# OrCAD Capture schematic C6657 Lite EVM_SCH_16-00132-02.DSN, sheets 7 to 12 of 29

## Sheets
7 PAGE25 : DSP_POWER 2: size C; title: DSP POWER 2
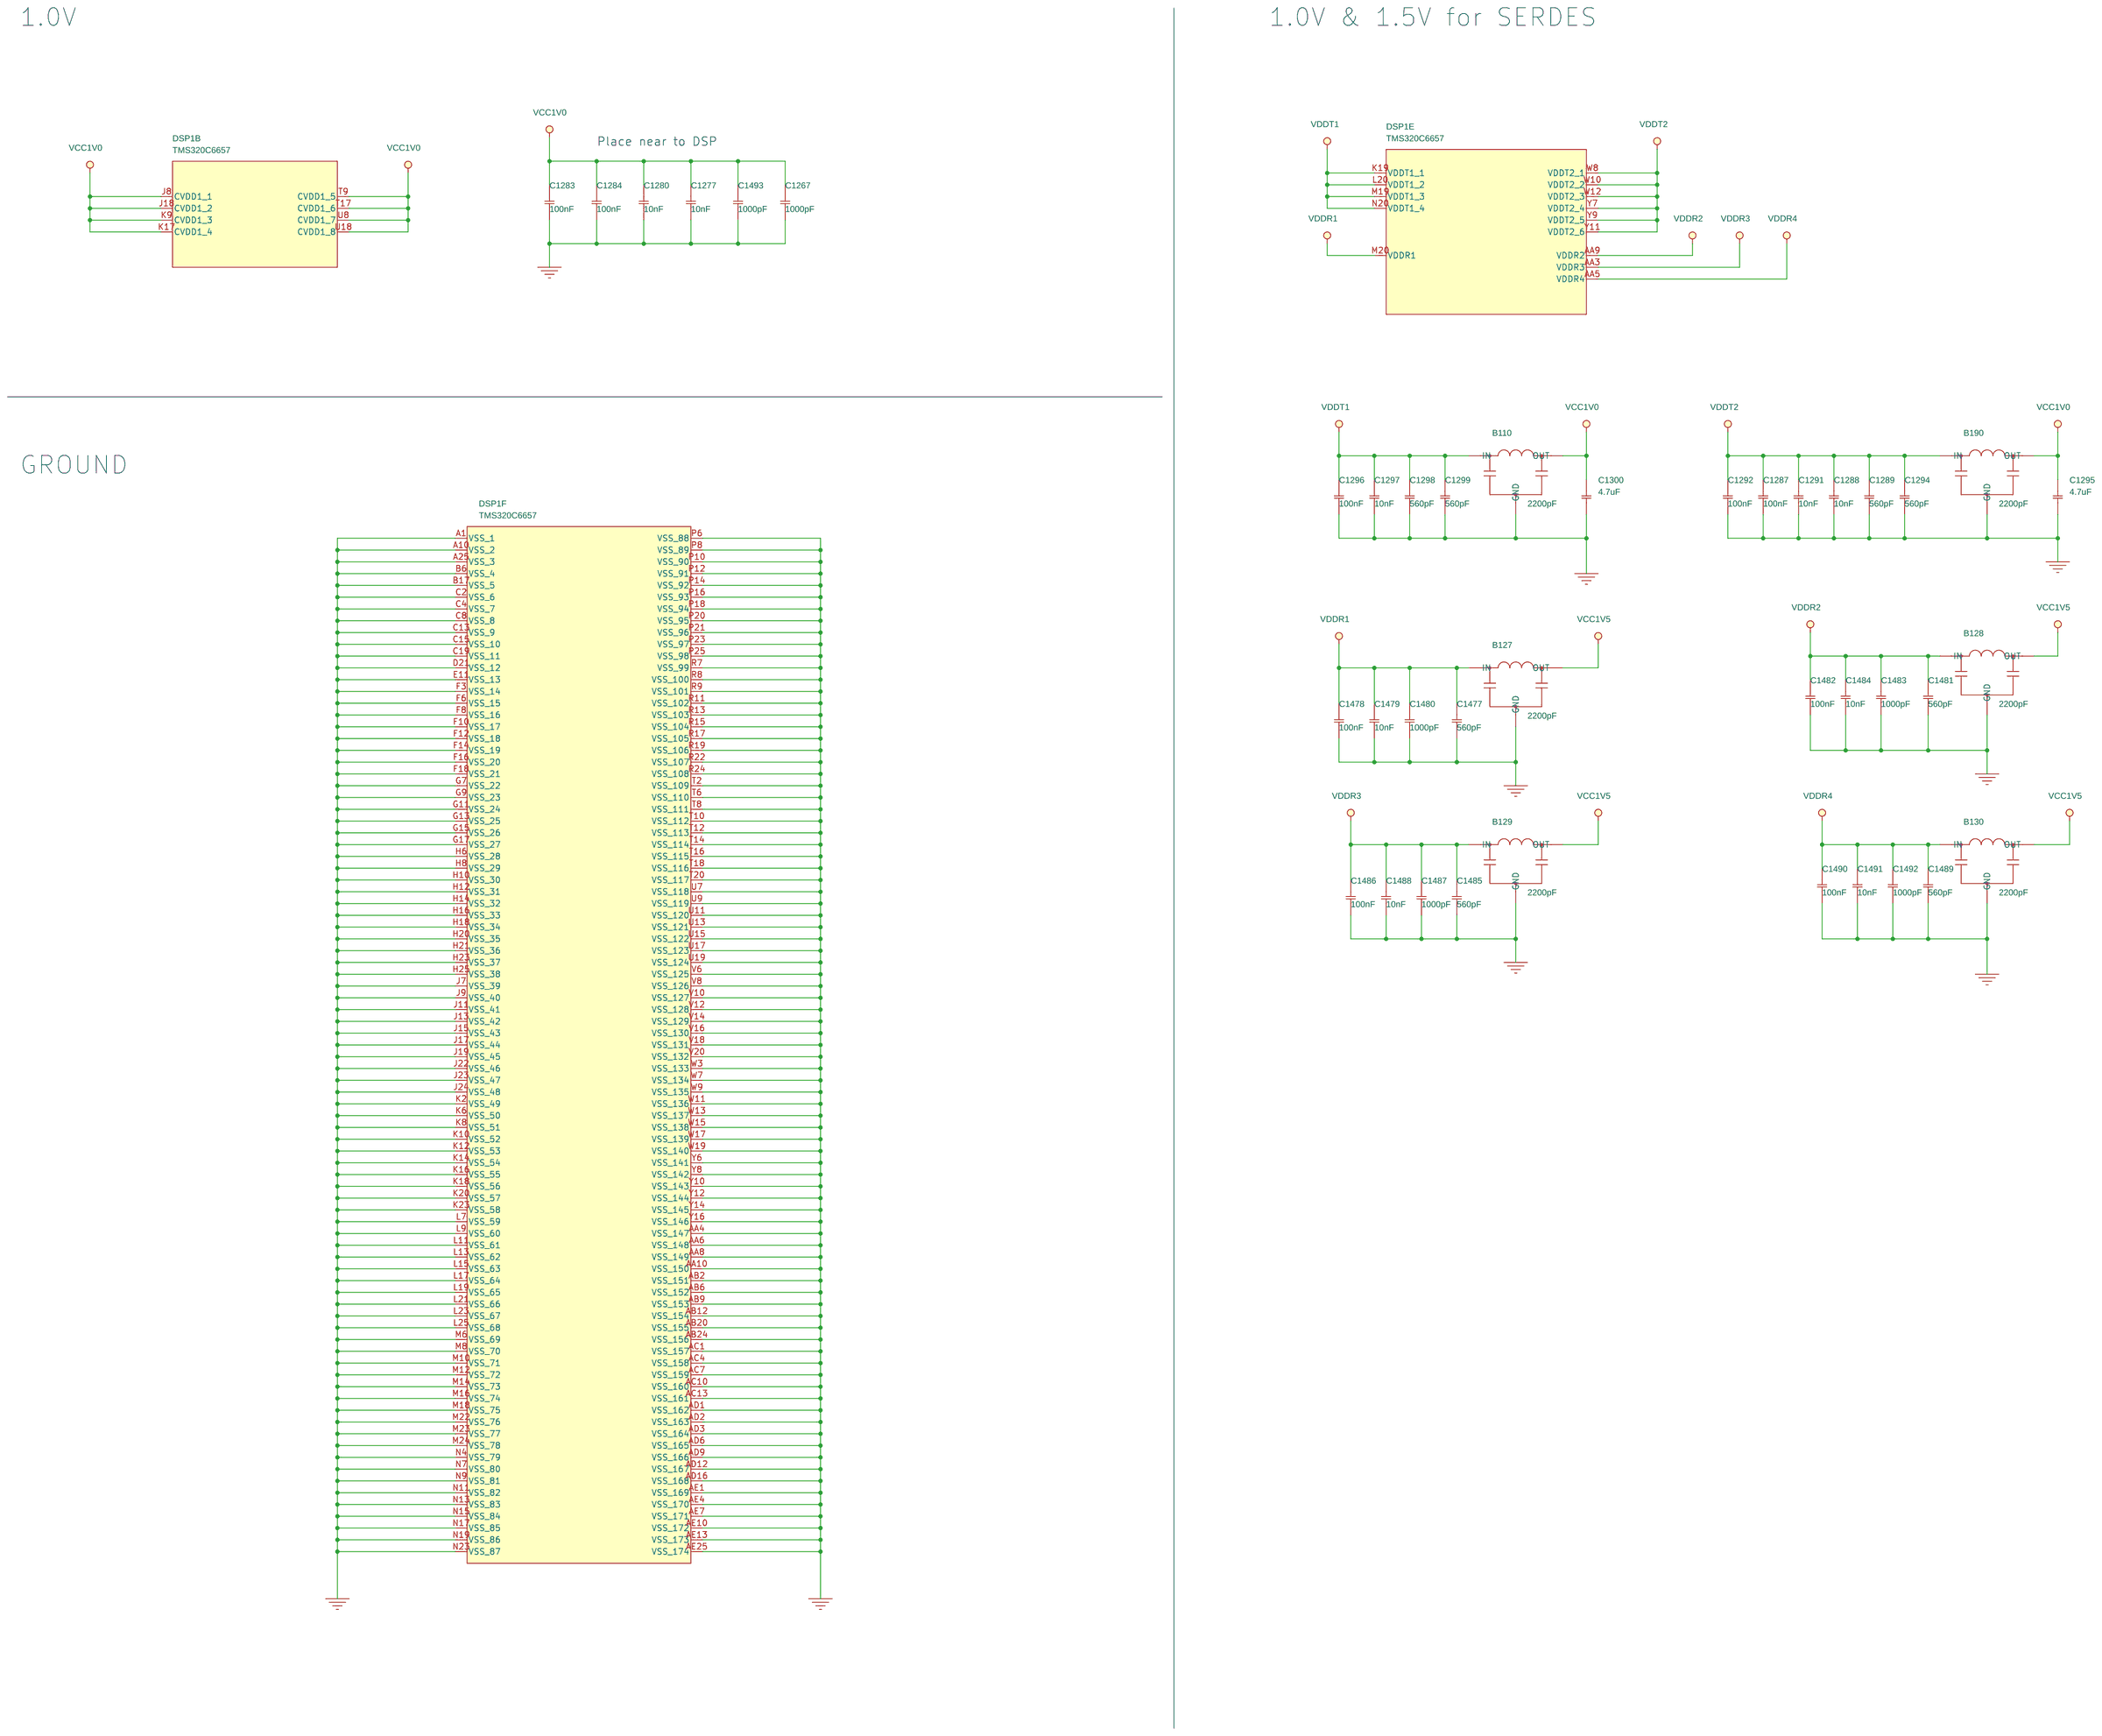
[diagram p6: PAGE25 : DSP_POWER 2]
8 PAGE15 : DDR3 & ECC: size C; title: DDR3 & ECC
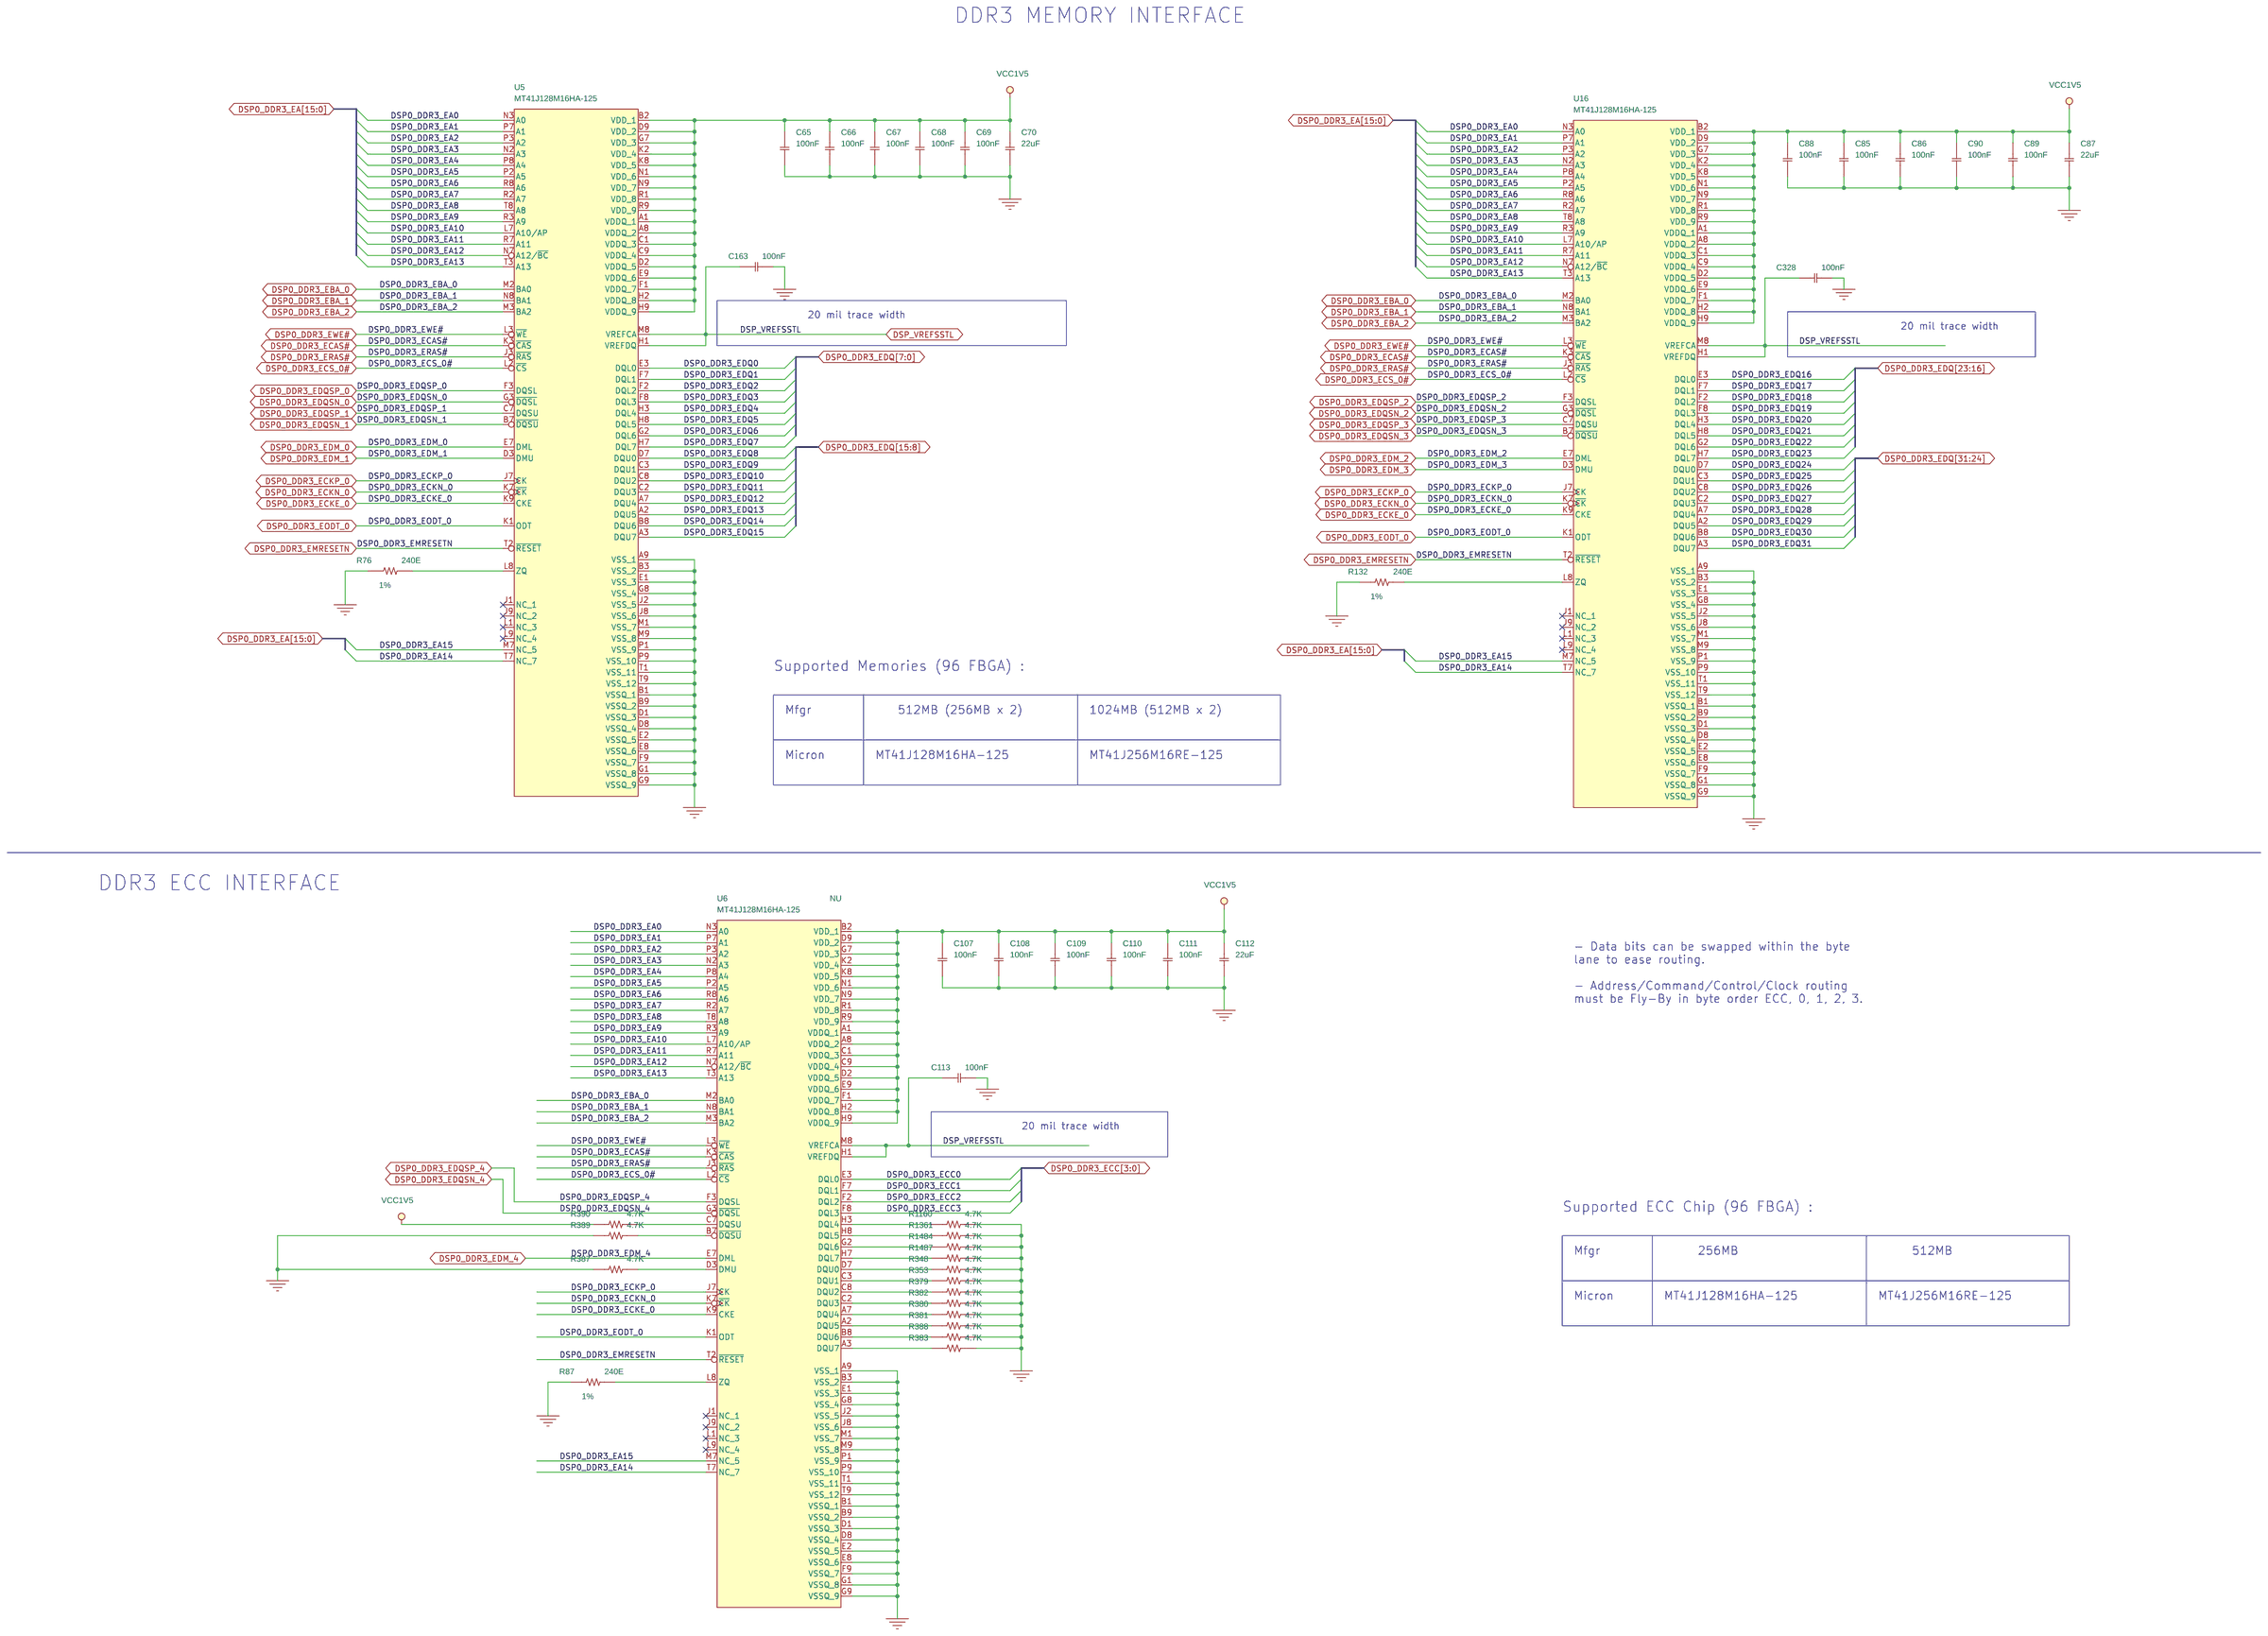
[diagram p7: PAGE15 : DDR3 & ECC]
9 PAGE24 : DSP_POWER 1: size C; title: DSP POWER 1
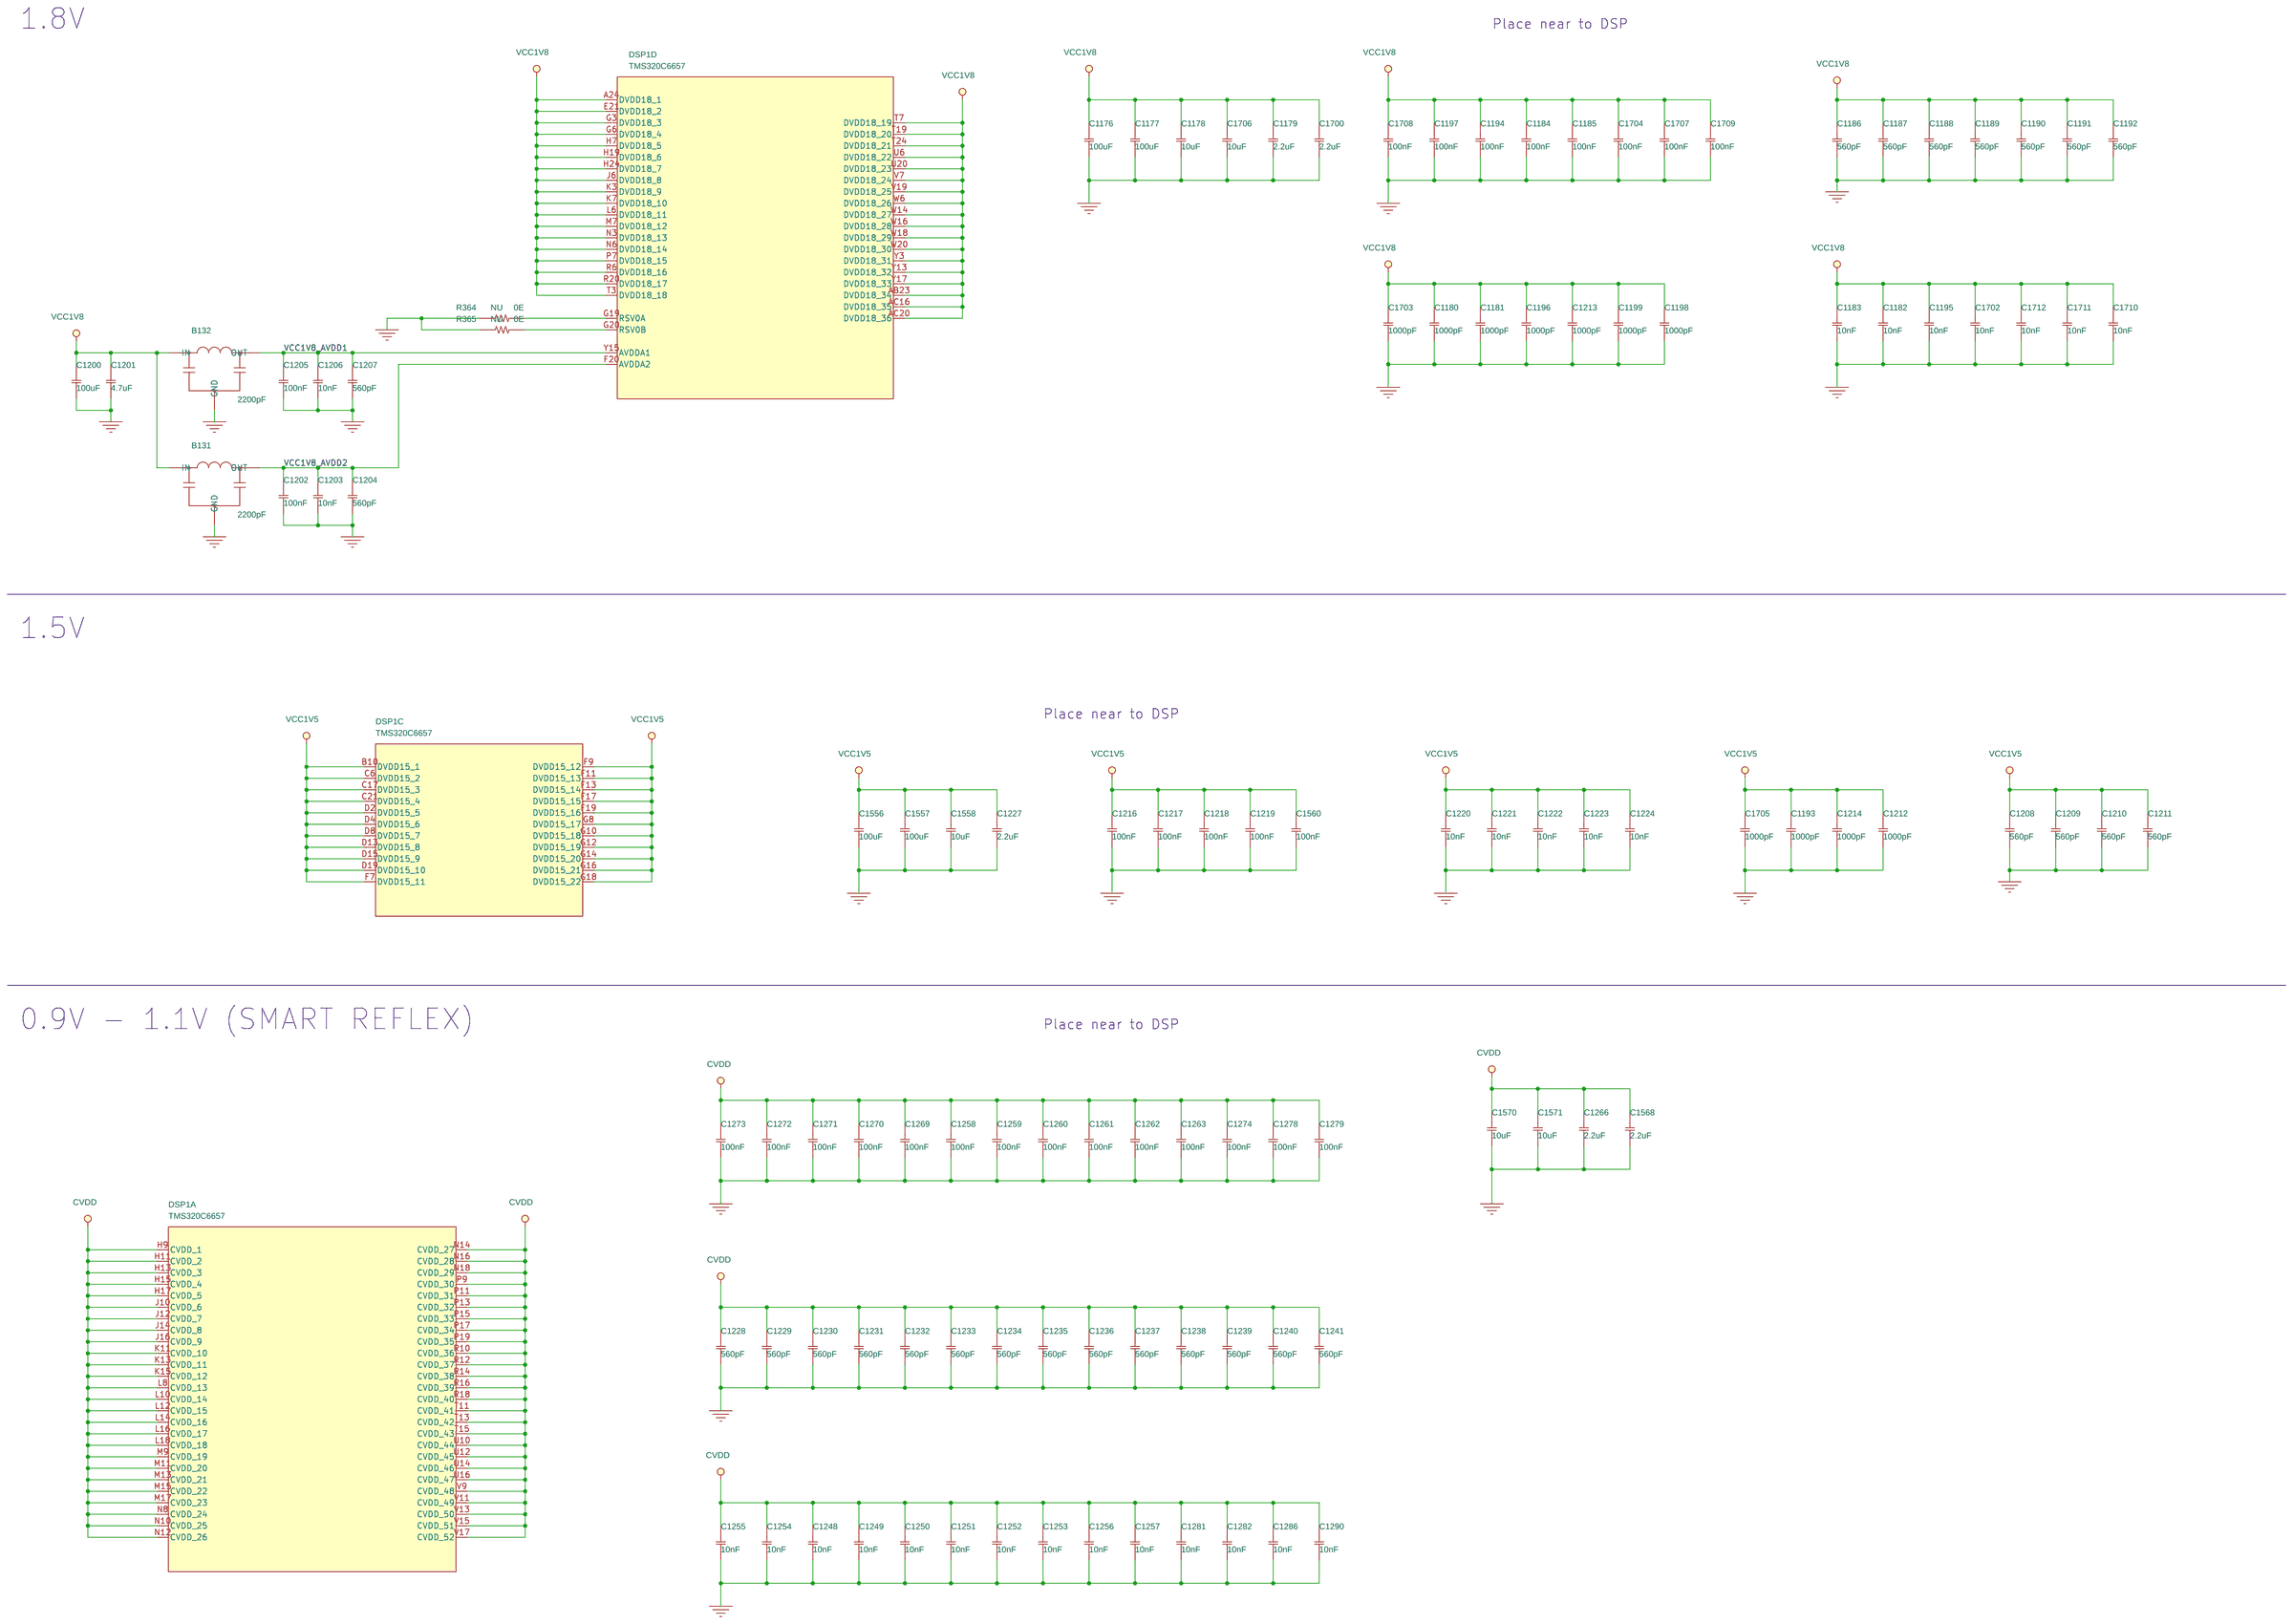
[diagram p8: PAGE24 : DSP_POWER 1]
10 PAGE10: MANAGEMENT MAP: title: MANAGEMENT MAP
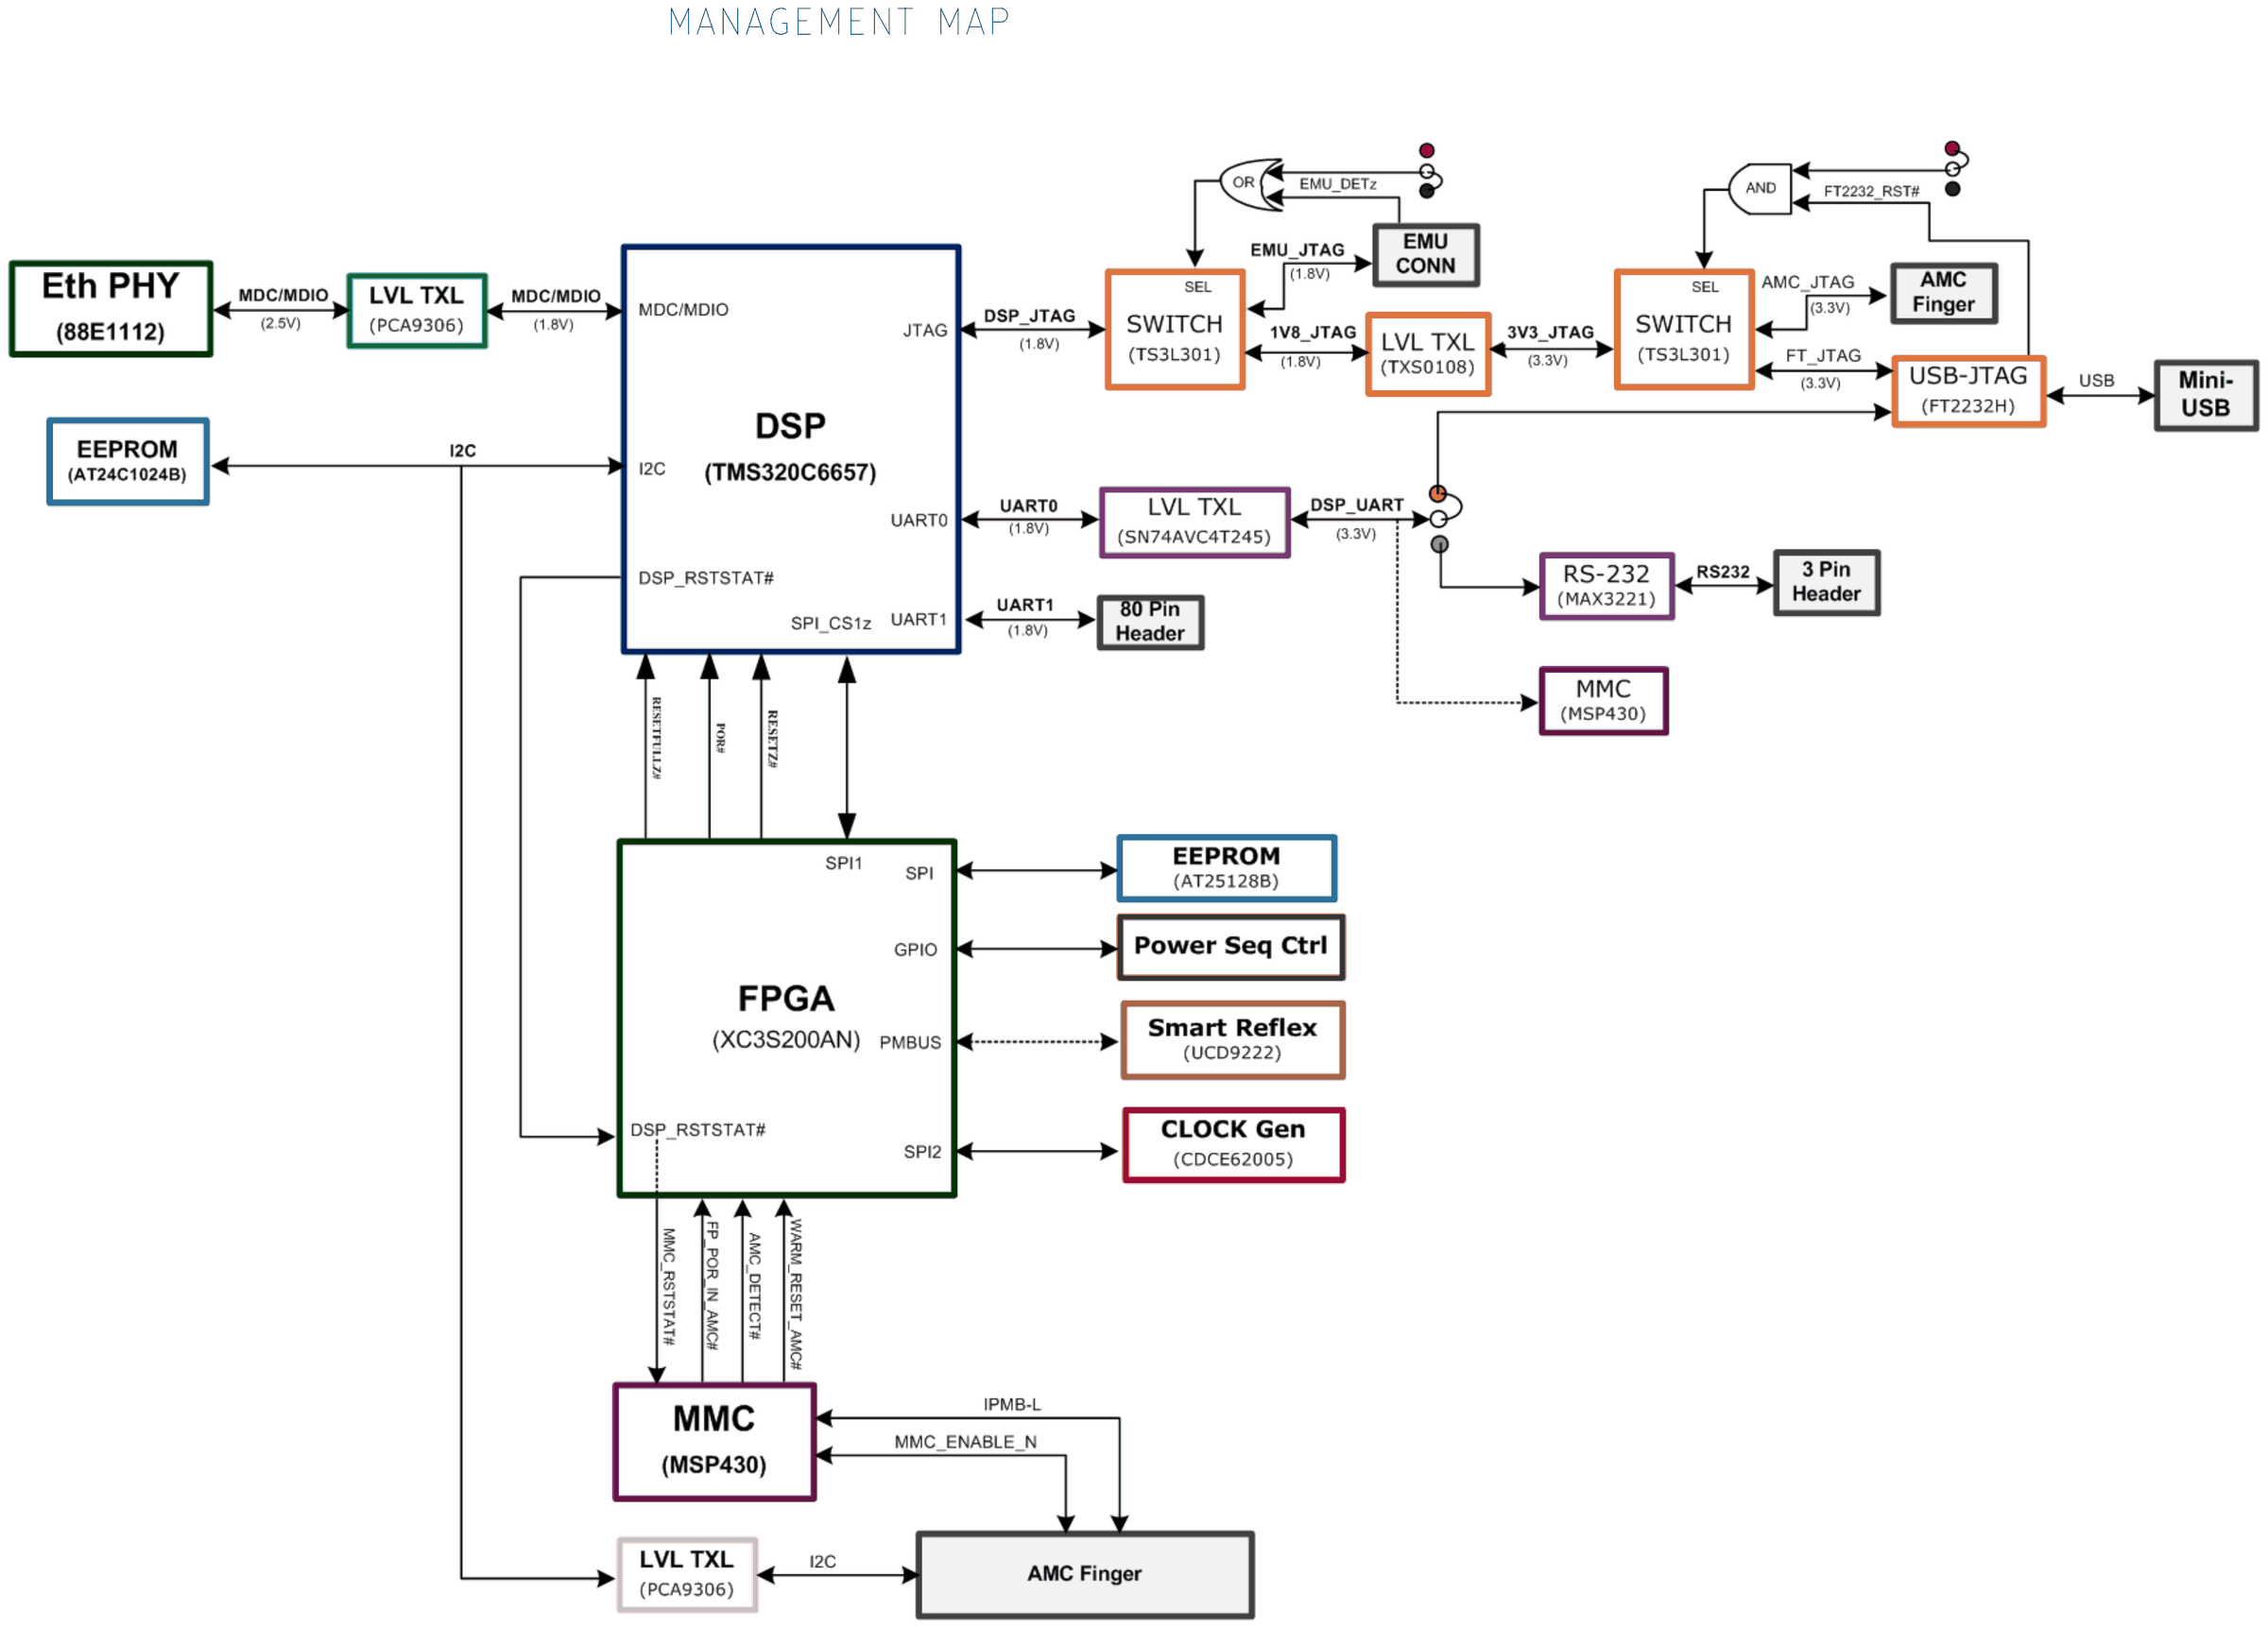
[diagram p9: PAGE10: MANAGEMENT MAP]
11 PAGE08 : CLOCK DIAGRAM: title: CLOCK DIAGRAM
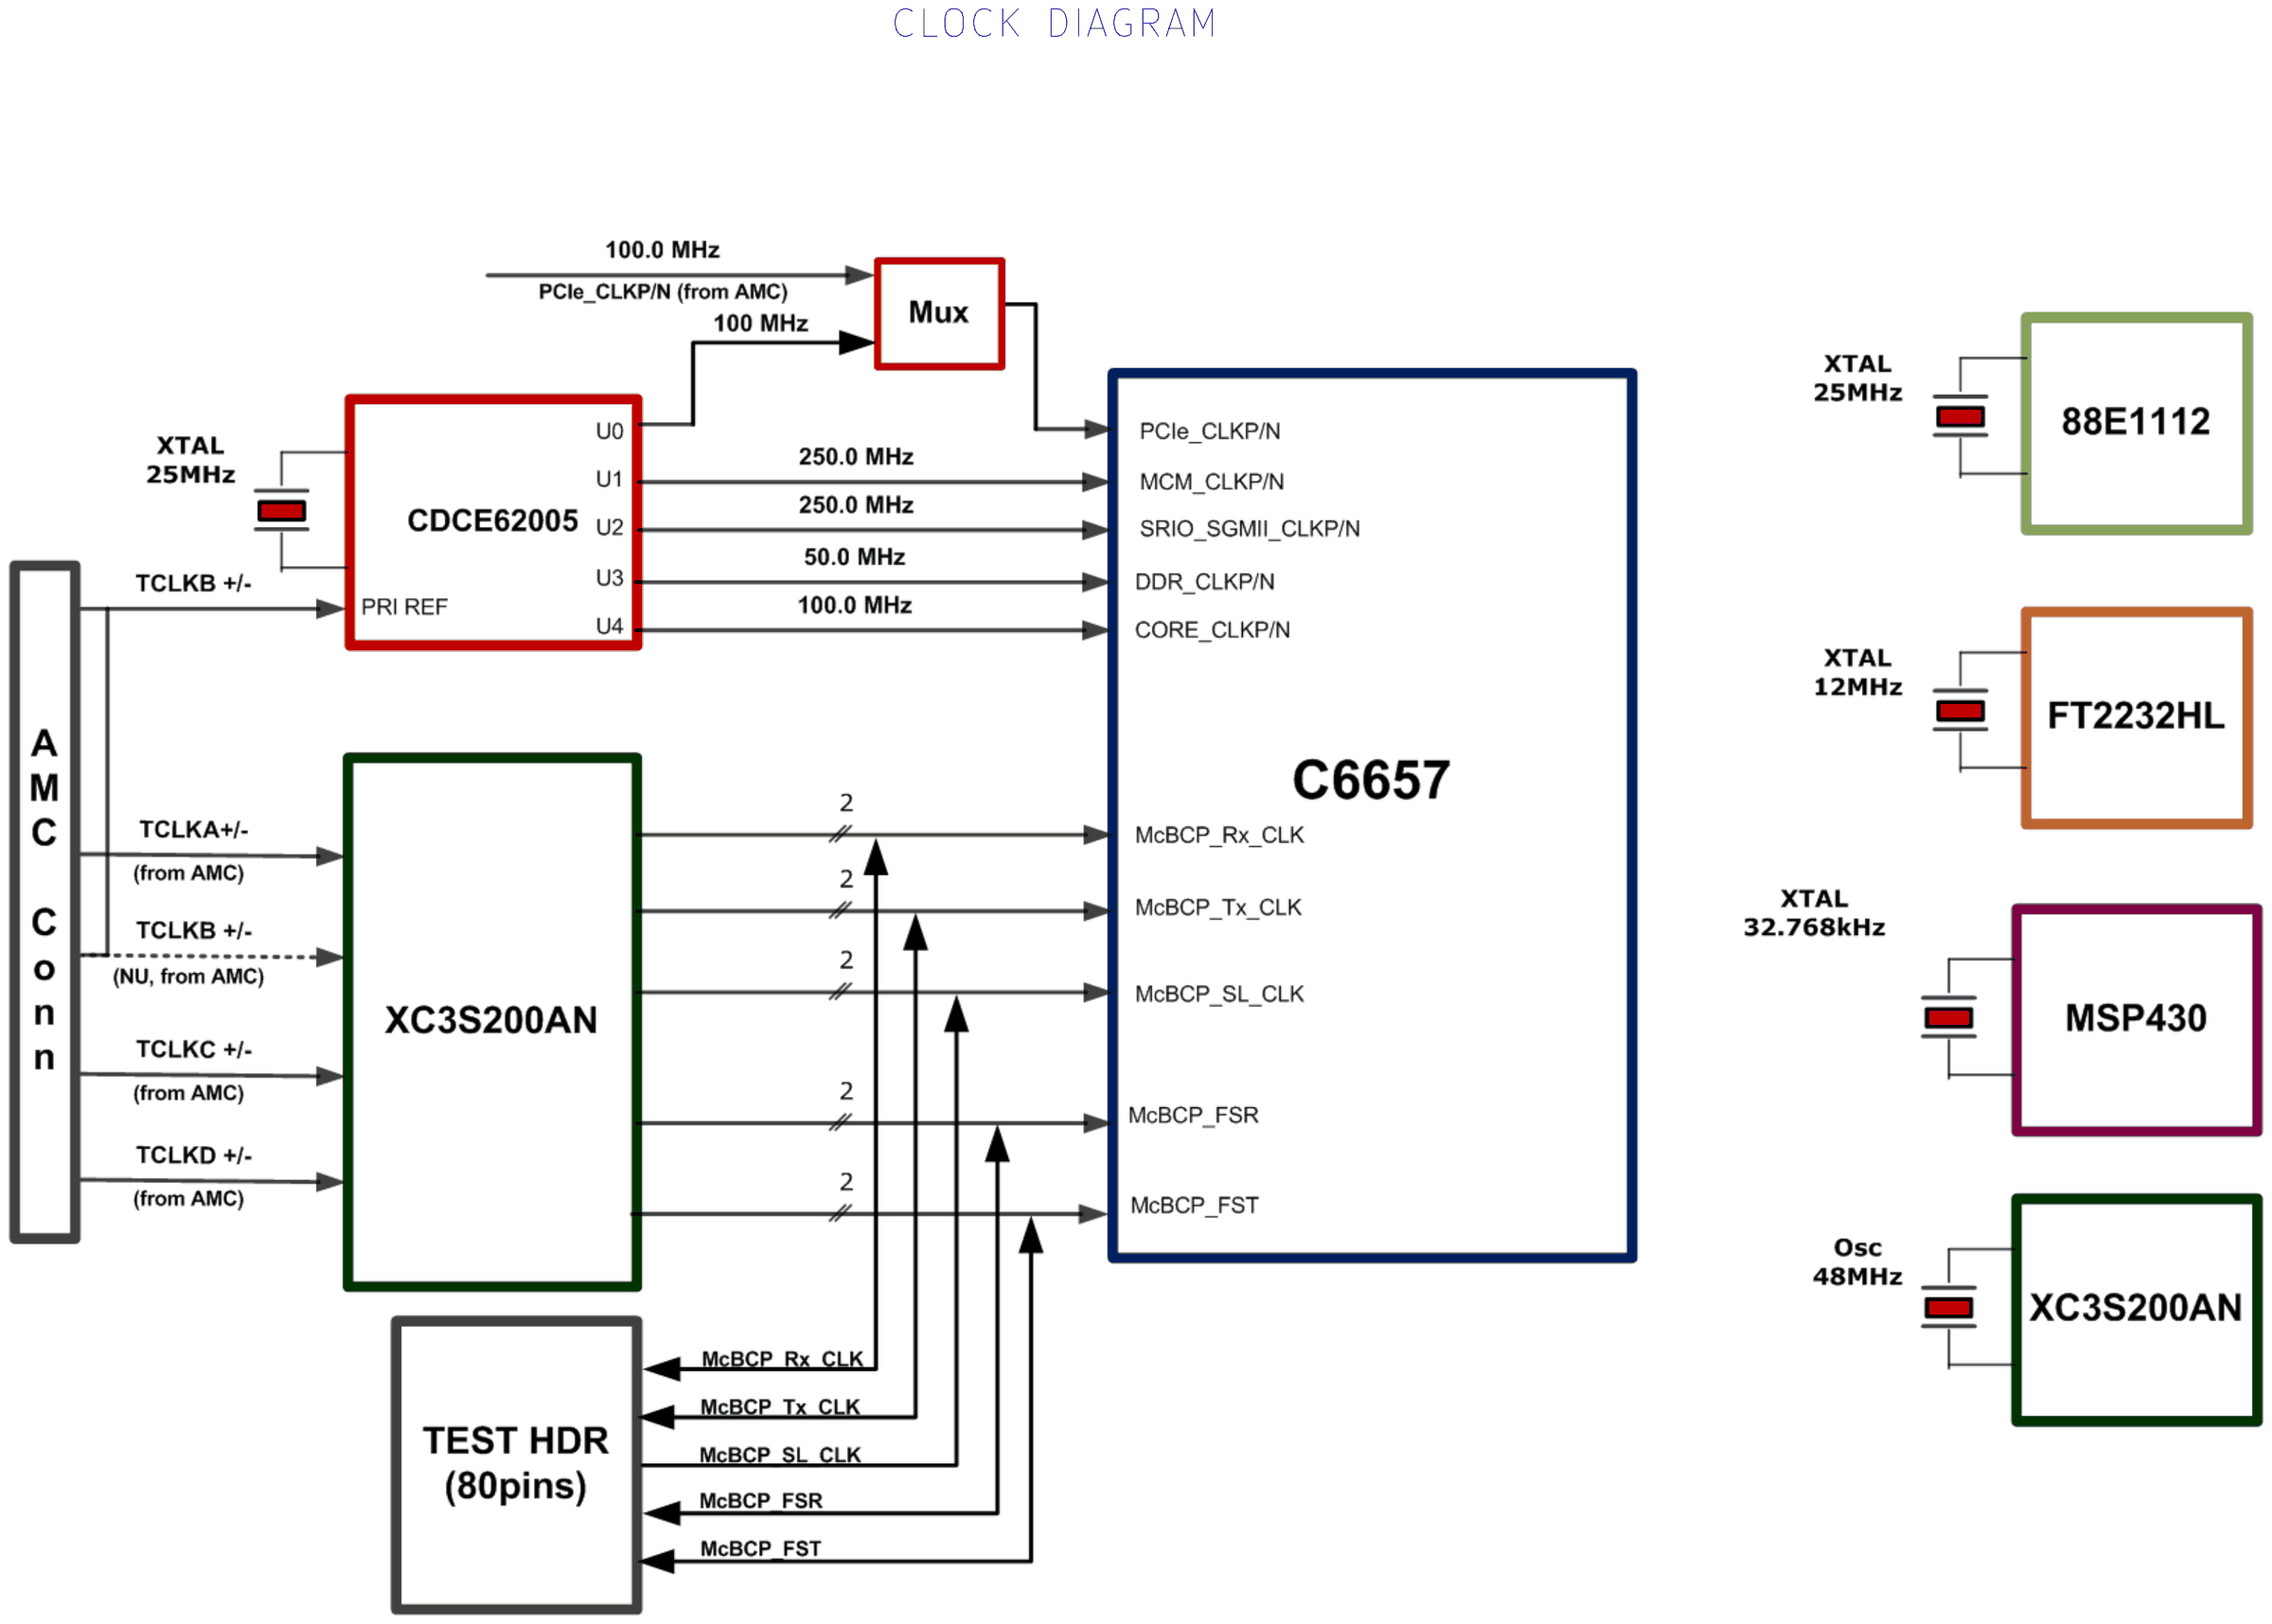
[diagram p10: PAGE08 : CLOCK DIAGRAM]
12 PAGE11 : AMC CONNECTOR: size C; title: AMC CONNECTOR
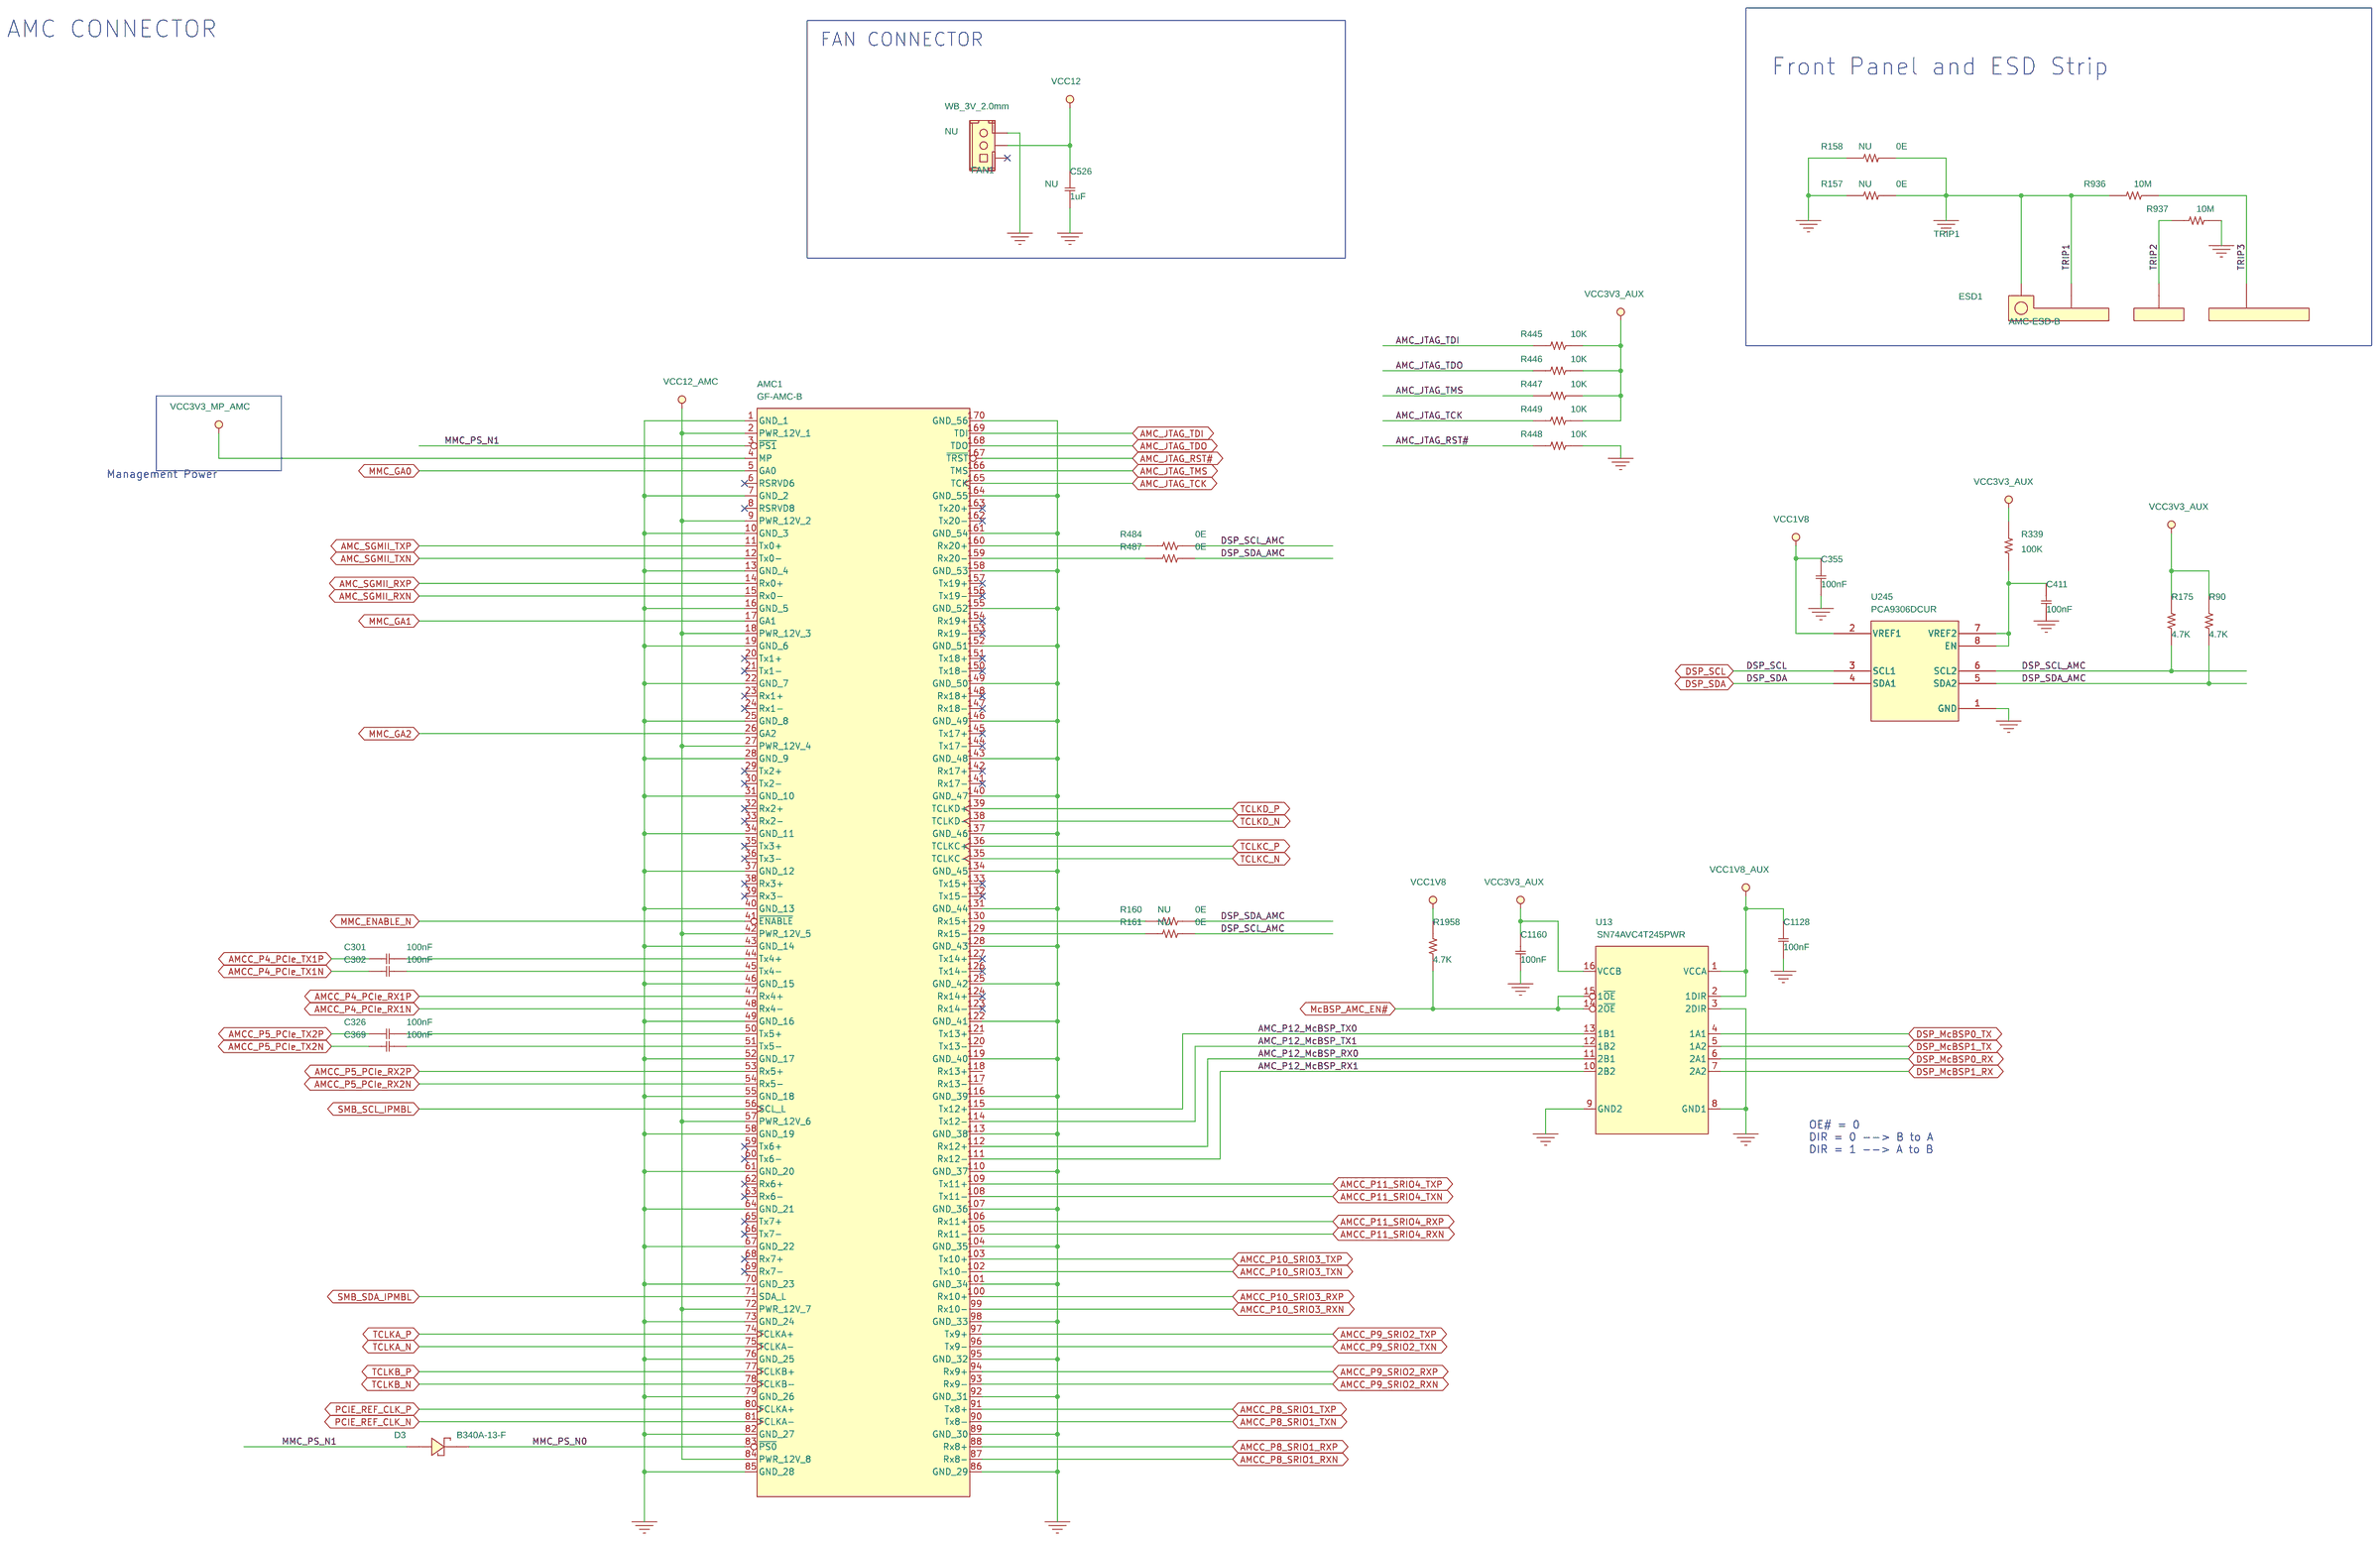
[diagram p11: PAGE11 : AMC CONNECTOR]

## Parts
sheet PAGE11 : AMC CONNECTOR
AMC1  GF-AMC-B  [GF-AMC-B]
C301  100nF  [C0402]
C302  100nF  [C0402]
C326  100nF  [C0402]
C355  100nF  [C0402]
C369  100nF  [C0402]
C411  100nF  [C0402]
C526  1uF  [C0402]
C1128  100nF  [C0402]
C1160  100nF  [C0402]
D3  B340A-13-F  [DIODE_2P_158_197X110]
ESD1  AMC-ESD-B  [AMC-ESD-B]
FAN1  WB_3V_2.0mm  [WHL3V-2M]
R90  4.7K  [R0402]
R157  0E  [R0402]
R158  0E  [R0402]
R160  0E  [R0402]
R161  0E  [R0402]
R175  4.7K  [R0402]
R339  100K  [R0402]
R445  10K  [R0402]
R446  10K  [R0402]
R447  10K  [R0402]
R448  10K  [R0402]
R449  10K  [R0402]
R484  0E  [R0402]
R487  0E  [R0402]
R936  10M  [R1206]
R937  10M  [R1206]
R1958  4.7K  [R0402]
U13  SN74AVC4T245PWR  [SOIC_16P_26_197x252]
U245  PCA9306DCUR  [SOIC_8P_20_79X122]
sheet PAGE15 : DDR3 & ECC
C65  100nF  [C0402]
C66  100nF  [C0402]
C67  100nF  [C0402]
C68  100nF  [C0402]
C69  100nF  [C0402]
C70  22uF  [C0805]
C85  100nF  [C0402]
C86  100nF  [C0402]
C87  22uF  [C0805]
C88  100nF  [C0402]
C89  100nF  [C0402]
C90  100nF  [C0402]
C107  100nF  [C0402]
C108  100nF  [C0402]
C109  100nF  [C0402]
C110  100nF  [C0402]
C111  100nF  [C0402]
C112  22uF  [C0805]
C113  100nF  [C0402]
C163  100nF  [C0402]
C328  100nF  [C0402]
R76  240E  [R0603]
R87  240E  [R0603]
R132  240E  [R0603]
R348  4.7K  [R0402]
R353  4.7K  [R0402]
R379  4.7K  [R0402]
R380  4.7K  [R0402]
R381  4.7K  [R0402]
R382  4.7K  [R0402]
R383  4.7K  [R0402]
R387  4.7K  [R0402]
R388  4.7K  [R0402]
R389  4.7K  [R0402]
R390  4.7K  [R0402]
R1160  4.7K  [R0402]
R1361  4.7K  [R0402]
R1484  4.7K  [R0402]
R1487  4.7K  [R0402]
U5  MT41J128M16HA-125  [BGA_96P_31_524X295_C14]
U6  MT41J128M16HA-125  [BGA_96P_31_524X295_C14]
U16  MT41J128M16HA-125  [BGA_96P_31_524X295_C14]
sheet PAGE24 : DSP_POWER 1
B131  2200pF  [L_3P_70_63X35]
B132  2200pF  [L_3P_70_63X35]
C1176  100uF  [C1206-1]
C1177  100uF  [C1206-1]
C1178  10uF  [C0603]
C1179  2.2uF  [C0402]
C1180  1000pF  [C0402]
C1181  1000pF  [C0402]
C1182  10nF  [C0402]
C1183  10nF  [C0402]
C1184  100nF  [C0402]
C1185  100nF  [C0402]
C1186  560pF  [C0402]
C1187  560pF  [C0402]
C1188  560pF  [C0402]
C1189  560pF  [C0402]
C1190  560pF  [C0402]
C1191  560pF  [C0402]
C1192  560pF  [C0402]
C1193  1000pF  [C0402]
C1194  100nF  [C0402]
C1195  10nF  [C0402]
C1196  1000pF  [C0402]
C1197  100nF  [C0402]
C1198  1000pF  [C0402]
C1199  1000pF  [C0402]
C1200  100uF  [C1206-1]
C1201  4.7uF  [C0603]
C1202  100nF  [C0402]
C1203  10nF  [C0402]
C1204  560pF  [C0402]
C1205  100nF  [C0402]
C1206  10nF  [C0402]
C1207  560pF  [C0402]
C1208  560pF  [C0402]
C1209  560pF  [C0402]
C1210  560pF  [C0402]
C1211  560pF  [C0402]
C1212  1000pF  [C0402]
C1213  1000pF  [C0402]
C1214  1000pF  [C0402]
C1216  100nF  [C0402]
C1217  100nF  [C0402]
C1218  100nF  [C0402]
C1219  100nF  [C0402]
C1220  10nF  [C0402]
C1221  10nF  [C0402]
C1222  10nF  [C0402]
C1223  10nF  [C0402]
C1224  10nF  [C0402]
C1227  2.2uF  [C0402]
C1228  560pF  [C0402]
C1229  560pF  [C0402]
C1230  560pF  [C0402]
C1231  560pF  [C0402]
C1232  560pF  [C0402]
C1233  560pF  [C0402]
C1234  560pF  [C0402]
C1235  560pF  [C0402]
C1236  560pF  [C0402]
C1237  560pF  [C0402]
C1238  560pF  [C0402]
C1239  560pF  [C0402]
C1240  560pF  [C0402]
C1241  560pF  [C0402]
C1248  10nF  [C0402]
C1249  10nF  [C0402]
C1250  10nF  [C0402]
C1251  10nF  [C0402]
C1252  10nF  [C0402]
C1253  10nF  [C0402]
C1254  10nF  [C0402]
C1255  10nF  [C0402]
C1256  10nF  [C0402]
C1257  10nF  [C0402]
C1258  100nF  [C0402]
C1259  100nF  [C0402]
C1260  100nF  [C0402]
C1261  100nF  [C0402]
C1262  100nF  [C0402]
C1263  100nF  [C0402]
C1266  2.2uF  [C0402]
C1269  100nF  [C0402]
C1270  100nF  [C0402]
C1271  100nF  [C0402]
C1272  100nF  [C0402]
C1273  100nF  [C0402]
C1274  100nF  [C0402]
C1278  100nF  [C0402]
C1279  100nF  [C0402]
C1281  10nF  [C0402]
C1282  10nF  [C0402]
C1286  10nF  [C0402]
C1290  10nF  [C0402]
C1556  100uF  [C1206-1]
C1557  100uF  [C1206-1]
C1558  10uF  [C0603]
C1560  100nF  [C0402]
C1568  2.2uF  [C0402]
C1570  10uF  [C0603]
C1571  10uF  [C0603]
C1700  2.2uF  [C0402]
C1702  10nF  [C0402]
C1703  1000pF  [C0402]
C1704  100nF  [C0402]
C1705  1000pF  [C0402]
C1706  10uF  [C0603]
C1707  100nF  [C0402]
C1708  100nF  [C0402]
C1709  100nF  [C0402]
C1710  10nF  [C0402]
C1711  10nF  [C0402]
C1712  10nF  [C0402]
R364  0E  [R0402]
R365  0E  [R0402]
sheet PAGE25 : DSP_POWER 2
B110  2200pF  [L_3P_70_63X35]
B127  2200pF  [L_3P_70_63X35]
B128  2200pF  [L_3P_70_63X35]
B129  2200pF  [L_3P_70_63X35]
B130  2200pF  [L_3P_70_63X35]
B190  2200pF  [L_3P_70_63X35]
C1267  1000pF  [C0402]
C1277  10nF  [C0402]
C1280  10nF  [C0402]
C1283  100nF  [C0402]
C1284  100nF  [C0402]
C1287  100nF  [C0402]
C1288  10nF  [C0402]
C1289  560pF  [C0402]
C1291  10nF  [C0402]
C1292  100nF  [C0402]
C1294  560pF  [C0402]
C1295  4.7uF  [C0603]
C1296  100nF  [C0402]
C1297  10nF  [C0402]
C1298  560pF  [C0402]
C1299  560pF  [C0402]
C1300  4.7uF  [C0603]
C1477  560pF  [C0402]
C1478  100nF  [C0402]
C1479  10nF  [C0402]
C1480  1000pF  [C0402]
C1481  560pF  [C0402]
C1482  100nF  [C0402]
C1483  1000pF  [C0402]
C1484  10nF  [C0402]
C1485  560pF  [C0402]
C1486  100nF  [C0402]
C1487  1000pF  [C0402]
C1488  10nF  [C0402]
C1489  560pF  [C0402]
C1490  100nF  [C0402]
C1491  10nF  [C0402]
C1492  1000pF  [C0402]
C1493  1000pF  [C0402]
DSP1  TMS320C6657  [BGA80P_38X38_625_SKT_EINF]  (sections A,B,C,D,E,F,G,H,I,J,K,L,M,N,O,P,Q,R,S,T)

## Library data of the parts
AMC1 = 00_GF-AMC-B_0: GOLD-FINGER  AMC-B  170P; Mfg: --NA--; Mfg Part#: --NA--; Oper. Temp. Range: --NA--; Package: --NA--; ProcessType: SMT; Remark: --NA--; RoHS: Yes; Vendor: --NA--; Vendor Part#: --NA--
C301 C302 C326 C369 C1160 = 11_C_0: CAP CER 0.1UF 10V 10% X5R 0402; Alt Mfg: Murata; Alt Mfg Part#: GRM155R61A104KA01D; Mfg: Yageo; Mfg Part#: CC0402KRX5R6BB104; Oper. Temp. Range: -55C to 85C; Package: 0402; ProcessType: SMT; RoHS: Yes; Tolerance: 10%; Vendor: DigiKey; Vendor Part#: 311-1336-1-ND; eI Part#: 03_00021_02
C65-C69 C85 C86 C88-C90 C107-C111 C113 C163 C328 C355 C411 C1128 C1184 C1185 C1194 C1197 C1202 C1205 C1216-C1219 C1258-C1263 C1269-C1274 C1278 C1279 C1283 C1284 C1287 C1292 C1296 C1478 C1482 C1486 C1490 C1560 C1704 C1707-C1709 = 11_C_0: CAP CER 0.1UF 10V 10% X5R 0402; Alt Mfg: Murata; Alt Mfg Part#: GRM155R61A104KA01D; Manufacture Part Number: 2238 787 15649||CC0402KRX7R7BB104; Mfg: Yageo; Mfg Part#: CC0402KRX5R6BB104; Oper. Temp. Range: -55C to 85C; Package: 0402; ProcessType: SMT; RoHS: Yes; Tolerance: 10%; Vendor: DigiKey; Vendor Part#: 311-1336-1-ND; eI Part#: 03_00021_02
C526 = 11_C_0: CAP CER 1.0UF 16V X5R 0402; Manufacture Part Number: C1005X5R0J105KT||C0402B105K007T; Mfg: TDK Corp; Mfg Part#: C1005X5R1C105K; Mounting Status: NU; Mounting_Status: NU; Oper. Temp. Range: -55C to 85C; Package: 0402; ProcessType: SMT; RoHS: Yes; Tolerance: 10%; Vendor: DigiKey; Vendor Part#: 445-4978-1-ND; eI Part#: 03_00264_01
D3 = Schottky_Diode: DIODE SCHOTTKY 3A 40V SMA; Mfg: Diodes Inc; Oper. Temp. Range: -55C to 85C; Package: DO-214AC; RoHS: Yes; Specifications: DIODE SCHOTTKY 3A 40V SMA; Vendor: DigiKey; Vendor Part#: B340A-FDICT-ND; eI Part#: 06_00002_01
ESD1 = 00_AMC-ESD-B_0: ESD Strip for AMC; Alt Mfg: -- NA --; Alt Mfg Part#: -- NA --; Mfg: -- NA --; Mfg Part#: -- NA --; Oper. Temp. Range: -- NA --; Package: -- NA --; ProcessType: SMT; RoHS: Yes; Tolerance: -- NA --; Vendor: -- NA --; Vendor Part#: -- NA --; eI Part#: -- NA --
FAN1 = 1655_WHL3V-2M_0: CONN HEADER 3POS VERT 2.5MM; Manufacture: TE Connectivity; Manufacture Part Number: 440054-3; Mfg: TE Connectivity; Mfg Part#: 440054-3; Mounting Status: NU; Mounting_Status: NU; Package: WB3P-2.00; Part Number: 1655303020; ProcessType: DIP; RoHS: Yes; Vendor: DigiKey; Vendor Part#: A100035-ND
R90 R175 R353 R382 R383 R387-R390 R1958 = 10_R_0: RES 4.7K OHM 1/10W 5% 0402 SMD; Alt Mfg: Yageo; Alt Mfg Part#: RC0402JR-074K7L; Mfg: Panasonic - ECG; Mfg Part#: ERJ-2GEJ472X; Oper. Temp. Range: -55C to 125C; Package: 0402; ProcessType: SMT; Remark: Alt part is 1/16W; RoHS: Yes; Tolerance: 5%; Vendor: DigiKey; Vendor Part#: P4.7KJCT-ND; eI Part#: 02_00023_01
R157 R158 R160 R161 R364 R365 = 10_R_0: RES ZERO OHM 1/10W 5% 0402 SMD; Alt Mfg: Yageo; Alt Mfg Part#: RC0402JR-070RL; Mfg: Panasonic - ECG; Mfg Part#: ERJ-2GE0R00X; Mounting Status: NU; Mounting_Status: NU; Oper. Temp. Range: -55C to 125C; Package: 0402; ProcessType: SMT; Remark: Alt part is 1/16W; RoHS: Yes; Tolerance: 5%; Vendor: DigiKey; Vendor Part#: P0.0JCT-ND; eI Part#: 02_00019_01
R339 = 10_R_0: RES 100K OHM 1/10W 1% 0402 SMD; Alt Mfg: Yageo; Alt Mfg Part#: RC0402FR-07100KL; Mfg: Panasonic - ECG; Mfg Part#: ERJ-2RKF1003X; Oper. Temp. Range: ±100ppm/°C; Package: 0402; ProcessType: SMT; RoHS: Yes; Tolerance: 1%; Vendor: DigiKey; Vendor Part#: P100KLCT-ND; eI Part#: 02_00262_01
R445-R449 = 10_R_0: RES 10.0K OHM 1/10W 1% 0402 SMD; Alt Mfg: Yageo; Alt Mfg Part#: RC0402FR-0710KL; Mfg: Panasonic - ECG; Mfg Part#: ERJ-2RKF1002X; Oper. Temp. Range: -55C ~ 125C; Package: 0402; ProcessType: SMT; Remark: Alt part is 1/16W; RoHS: Yes; Tolerance: 1%; Vendor: DigiKey; Vendor Part#: P10.0KLCT-ND; eI Part#: 02_00027_01
R484 R487 = 10_R_0: RES ZERO OHM 1/10W 5% 0402 SMD; Alt Mfg: Yageo; Alt Mfg Part#: RC0402JR-070RL; Mfg: Panasonic - ECG; Mfg Part#: ERJ-2GE0R00X; Oper. Temp. Range: -55C to 125C; Package: 0402; ProcessType: SMT; Remark: Alt part is 1/16W; RoHS: Yes; Tolerance: 5%; Vendor: DigiKey; Vendor Part#: P0.0JCT-ND; eI Part#: 02_00019_01
R936 R937 = 10_R_0: RES 10M OHM 1/4W 5% 1206 PKG; Alt Mfg: Yageo; Alt Mfg Part#: RC1206JR-0710ML; Mfg: Panasonic - ECG; Mfg Part#: ERJ-8GEYJ106V; Oper. Temp. Range: -400/ +150ppm/°C; Package: 1206; Remark: 1/4W; RoHS: Yes; Specifications: RES 10M OHM 1/4W 5% 1206 PKG; Vendor: DigiKey; Vendor Part#: P10MECT-ND; eI Part#: 02_00741_01
U13 = SN74AVC4T245PWR: IC BUS TRANSCVR 4BIT 16TSSOP; Mfg: Texas Instruments; Oper. Temp. Range: -40°C ~ 85°C; Package: 16-TSSOP; RoHS: Yes; Specifications: IC BUS TRANSCVR 4BIT 16TSSOP; Vendor: Texas Instruments; eI Part#: 01_00045_01
U245 = PCA9306: IC, Dual I2C Voltage Translator; Alt Mfg: NXP Semiconductors; Alt Mfg Part#: PCA9306DC1,125; Mfg: Texas Instruments; Oper. Temp. Range: -40C to 85C; Package: 8-VSSOP; RoHS: Yes; Specifications: IC, Dual I2C Voltage Translator; Vendor: Digikey; Vendor Part#: 296-17988-1-ND; eI Part#: 01_00044_01
C70 C87 C112 = 11_C_0: CAP CER 22UF 10V X5R 0805; Manufacture Part Number: C0805B226M007T; Mfg: Taiyo Yuden; Mfg Part#: LMK212BJ226MG-T; Oper. Temp. Range: -55C to 85C; Package: 0805; ProcessType: SMT; RoHS: Yes; Tolerance: 20%; Vendor: DigiKey; Vendor Part#: 587-1958-1-ND; Voltage: 10V; eI Part#: 03_00263_01
R76 R87 R132 = 10_R_0: RES 240 OHM 1/10W 1% 0603 SMD; Mfg: Panasonic - ECG; Mfg Part#: ERJ-3EKF2400V; Package: 0603; ProcessType: SMT; RoHS: Yes; Tolerance: 1%; Vendor: DigiKey; Vendor Part#: P240HCT-ND; eI Part#: 02_00734_01
R348 R379-R381 R1160 R1361 R1484 R1487 = 10_R_0: RES 4.7K OHM 1/10W 5% 0402 SMD; Alt Mfg: Yageo; Alt Mfg Part#: RC0402JR-074K7L; Manufacture Part Number: 0402WGJ0000TCE||RC0402JR-070RL||RM04JTN0; Mfg: Panasonic - ECG; Mfg Part#: ERJ-2GEJ472X; Oper. Temp. Range: -55C to 125C; Package: 0402; ProcessType: SMT; Remark: Alt part is 1/16W; RoHS: Yes; Tolerance: 5%; Vendor: DigiKey; Vendor Part#: P4.7KJCT-ND; eI Part#: 02_00023_01
U5 U16 = MT41J128M16HA-125: IC DDR3 SDRAM 2GBIT 96FBGA; Alt Mfg: Micron; Alt Mfg Part#: MT41J128M16JT-125:K; Manufacture Part Number: K4B1G1646G-BCH9; Mfg: Micron; Mfg Part#: MT41J128M16HA-125G; Package: FBGA96; ProcessType: SMT; RoHS: Yes; Vendor: DigiKey; Vendor Part#: MT41J128M16HA-125G:D-ND; eI Part#: 01_00730_01
U6 = MT41J128M16HA-125: IC DDR3 SDRAM 2GBIT 96FBGA; Alt Mfg: Micron; Alt Mfg Part#: MT41J128M16JT-125:K; Manufacture Part Number: K4B1G1646G-BCH9; Mfg: Micron; Mfg Part#: MT41J128M16HA-125G; Mounting Status: NU; Mounting_Status: NU; Package: FBGA96; ProcessType: SMT; RoHS: Yes; Vendor: DigiKey; Vendor Part#: MT41J128M16HA-125G:D-ND; eI Part#: 01_00730_01
B110 B127-B132 B190 = 1212_FILTER_NFW31SP106X1E4L_0: FILTER LC HIGH FREQ 2200PF 0603; Manufacture Part Number: NFM18CC222R1C3D; Mfg: Murata; Mfg Part#: NFM18CC222R1C3D; Oper. Temp. Range: -55C to 125C; Package: 0603; ProcessType: SMT; RoHS: Yes; Tolerance: 20%; Vendor: DigiKey; Vendor Part#: NFM18CC222R1C3D-ND; eI Part#: 04_00026_01
C1176 C1177 C1200 C1556 C1557 = 11_C_0: CAP CER 100UF 6.3V 20% X5R 1206; Manufacture Part Number: JMK316BJ107ML-T; Mfg: Taiyo Yuden; Mfg Part#: JMK316BJ107ML-T; Oper. Temp. Range: -55C to 85C; Package: 1206; ProcessType: SMT; RoHS: Yes; Tolerance: 20%; Vendor: DigiKey; Vendor Part#: 587-1963-1-ND; eI Part#: 03_00380_04
C1178 C1558 C1570 C1571 C1706 = 11_C_0: CAP CER 10UF 6.3V 20% X5R 0603; Manufacture Part Number: C1608X5R0J106MT||2255 206 13776||CC0603MRX5R5BB106; Mfg: Murata; Mfg Part#: GRM188R60J106ME47D; Oper. Temp. Range: -55C to 85C; Package: 0603; ProcessType: SMT; RoHS: Yes; Tolerance: 20%; Vendor: DigiKey; Vendor Part#: 490-3896-1-ND; eI Part#: 03_00058_03
C1179 C1227 C1266 = 11_C_0: CAP CER 2.2UF 10V 10% X5R 0402; Mfg: TDK Corp; Mfg Part#: C1005X5R1A225K; Oper. Temp. Range: -55C to 105C; Package: 0402; ProcessType: SMT; RoHS: Yes; Specifications: CAP CER 47UF 6.3V 20% X5R 0805; Tolerance: 10%; Vendor: DigiKey; Vendor Part#: 445-7392-1-ND; eI Part#: 03_00471_01
C1180 C1181 C1193 C1196 C1198 C1199 C1212-C1214 C1267 C1480 C1483 C1487 C1492 C1493 C1703 C1705 = 11_C_0: CAP CER 1000PF 25V X7R 0402; Manufacture Part Number: 223858715623||CC0402KRX7R9BB102; Mfg: Johnson Dielectrics Inc; Mfg Part#: 250R07W102KV4T; Oper. Temp. Range: -55C to 125C; Package: 0402; ProcessType: SMT; RoHS: Yes; Tolerance: 10%; Vendor: DigiKey; Vendor Part#: 709-1131-1-ND; eI Part#: 03_00289_01
C1182 C1183 C1195 C1203 C1206 C1220-C1224 C1248-C1257 C1277 C1280-C1282 C1286 C1288 C1290 C1291 C1297 C1479 C1484 C1488 C1491 C1702 C1710-C1712 = 11_C_0: CAP 10nF 16V CERAMIC 0402 SMD; Alt Mfg: Murata; Alt Mfg Part#: GRM155R71C103KA01D; Manufacture Part Number: C1005X7R1C103K||2238 787 15636||CC0402KRX7R7BB103; Mfg: Panasonic - ECG; Mfg Part#: ECJ-0EB1C103K; Oper. Temp. Range: -55C to 125C; Package: 0402; ProcessType: SMT; RoHS: Yes; Tolerance: 10%; Vendor: DigiKey; Vendor Part#: PCC103BQCT-ND; eI Part#: 03_00025_01
C1186-C1192 C1204 C1207-C1211 C1228-C1241 C1289 C1294 C1298 C1299 C1477 C1481 C1485 C1489 = 11_C_0: CAP CER 560PF 50V 10% X7R 0402; Alt Mfg: AVX; Alt Mfg Part#: 04025C561KAT2A; Manufacture Part Number: 223858715619; Mfg: Yageo; Mfg Part#: CC0402KRX7R9BB561; Oper. Temp. Range: -55C to 125C; Package: 0402; ProcessType: SMT; RoHS: Yes; Tolerance: 10%; Vendor: DigiKey; Vendor Part#: 311-1029-1-ND; eI Part#: 03_00108_05
C1201 C1295 C1300 = 11_C_0: CAP CER 4.7UF 10V Y5V 0603; Manufacture Part Number: GRM188R60J475K||C1608X5R0J475KT; Mfg: Murata; Mfg Part#: GRM188F51A475ZE20D; Oper. Temp. Range: -55C to 85C; Package: 0603; ProcessType: SMT; RoHS: Yes; Tolerance: 10%; Vendor: DigiKey; Vendor Part#: 490-3302-1-ND; eI Part#: 03_00276_01
C1568 C1700 = 11_C_0: CAP CER 2.2UF 10V 10% X5R 0402; Manufacture Part Number: JMK316BJ107ML-T; Mfg: TDK Corp; Mfg Part#: C1005X5R1A225K; Oper. Temp. Range: -55C to 85C; Package: 0402; ProcessType: SMT; RoHS: Yes; Tolerance: 10%; Vendor: DigiKey; Vendor Part#: 445-7392-1-ND; eI Part#: 03_00471_01
DSP1 = TMS320C6657: TI DSP, Dual C66x™ DSP Cores; Mfg: Texas Instruments; RoHS: Yes; Vendor: Texas Instruments; eI Part#: 01_00878_01

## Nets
GND: AMC1.1(GND) AMC1.7(GND_2) AMC1.10(GND_3) AMC1.13(GND_4) AMC1.16(GND_5) AMC1.19(GND_6) AMC1.22(GND_7) AMC1.25(GND_8) AMC1.28(GND_9) AMC1.31(GND_10) AMC1.34(GND_11) AMC1.37(GND_12) AMC1.40(GND_13) AMC1.43(GND_14) AMC1.46(GND_15) AMC1.49(GND_16) AMC1.52(GND_17) AMC1.55(GND_18) AMC1.58(GND_19) AMC1.61(GND_20) AMC1.64(GND_21) AMC1.67(GND_22) AMC1.70(GND_23) AMC1.73(GND_24) AMC1.76(GND_25) AMC1.79(GND_26) AMC1.82(GND_27) AMC1.85(GND_28) AMC1.86(GND_29) AMC1.89(GND_30) AMC1.92(GND_31) AMC1.95(GND_32) AMC1.98(GND_33) AMC1.101(GND_34) AMC1.104(GND_35) AMC1.107(GND_36) AMC1.110(GND_37) AMC1.113(GND_38) AMC1.116(GND_39) AMC1.119(GND_40) AMC1.122(GND_41) AMC1.125(GND_42) AMC1.128(GND_43) AMC1.131(GND_44) AMC1.134(GND_45) AMC1.137(GND_46) AMC1.140(GND_47) AMC1.143(GND_48) AMC1.146(GND_49) AMC1.149(GND_50) AMC1.152(GND_51) AMC1.155(GND_52) AMC1.158(GND_53) AMC1.161(GND_54) AMC1.164(GND_55) AMC1.170(GND_56) B110.2(GND) B127.2(GND) B128.2(GND) B129.2(GND) B130.2(GND) B131.2(GND) B132.2(GND) B190.2(GND) C65.2 C66.2 C67.2 C68.2 C69.2 C70.2 C85.2 C86.2 C87.2 C88.2 C89.2 C90.2 C107.2 C108.2 C109.2 C110.2 C111.2 C112.2 C113.2 C163.2 C328.2 C355.1 C411.2 C526.2 C1128.1 C1160.1 C1176.2 C1177.2 C1178.2 C1179.2 C1180.2 C1181.2 C1182.2 C1183.2 C1184.2 C1185.2 C1186.2 C1187.2 C1188.2 C1189.2 C1190.2 C1191.2 C1192.2 C1193.2 C1194.2 C1195.2 C1196.2 C1197.2 C1198.2 C1199.2 C1200.2 C1201.2 C1202.2 C1203.2 C1204.2 C1205.2 C1206.2 C1207.2 C1208.2 C1209.2 C1210.2 C1211.2 C1212.2 C1213.2 C1214.2 C1216.2 C1217.2 C1218.2 C1219.2 C1220.2 C1221.2 C1222.2 C1223.2 C1224.2 C1227.2 C1228.2 C1229.2 C1230.2 C1231.2 C1232.2 C1233.2 C1234.2 C1235.2 C1236.2 C1237.2 C1238.2 C1239.2 C1240.2 C1241.2 C1248.2 C1249.2 C1250.2 C1251.2 C1252.2 C1253.2 C1254.2 C1255.2 C1256.2 C1257.2 C1258.2 C1259.2 C1260.2 C1261.2 C1262.2 C1263.2 C1266.2 C1267.2 C1269.2 C1270.2 C1271.2 C1272.2 C1273.2 C1274.2 C1277.2 C1278.2 C1279.2 C1280.2 C1281.2 C1282.2 C1283.2 C1284.2 C1286.2 C1287.2 C1288.2 C1289.2 C1290.2 C1291.2 C1292.2 C1294.2 C1295.2 C1296.2 C1297.2 C1298.2 C1299.2 C1300.2 C1477.2 C1478.2 C1479.2 C1480.2 C1481.2 C1482.2 C1483.2 C1484.2 C1485.2 C1486.2 C1487.2 C1488.2 C1489.2 C1490.2 C1491.2 C1492.2 C1493.2 C1556.2 C1557.2 C1558.2 C1560.2 C1568.2 C1570.2 C1571.2 C1700.2 C1702.2 C1703.2 C1704.2 C1705.2 C1706.2 C1707.2 C1708.2 C1709.2 C1710.2 C1711.2 C1712.2 DSP1.A1(VSS_1) DSP1.A10(VSS_2) DSP1.A25(VSS_3) DSP1.AA4(VSS_147) DSP1.AA6(VSS_148) DSP1.AA8(VSS_149) DSP1.AA10(VSS_150) DSP1.AB2(VSS_151) DSP1.AB6(VSS_152) DSP1.AB9(VSS_153) DSP1.AB12(VSS_154) DSP1.AB20(VSS_155) DSP1.AB24(VSS_156) DSP1.AC1(VSS_157) DSP1.AC4(VSS_158) DSP1.AC7(VSS_159) DSP1.AC10(VSS_160) DSP1.AC13(VSS_161) DSP1.AD1(VSS_162) DSP1.AD2(VSS_163) DSP1.AD3(VSS_164) DSP1.AD6(VSS_165) DSP1.AD9(VSS_166) DSP1.AD12(VSS_167) DSP1.AD16(VSS_168) DSP1.AE1(VSS_169) DSP1.AE4(VSS_170) DSP1.AE7(VSS_171) DSP1.AE10(VSS_172) DSP1.AE13(VSS_173) DSP1.AE25(VSS_174) DSP1.B6(VSS_4) DSP1.B17(VSS_5) DSP1.C2(VSS_6) DSP1.C4(VSS_7) DSP1.C8(VSS_8) DSP1.C13(VSS_9) DSP1.C15(VSS_10) DSP1.C19(VSS_11) DSP1.D21(VSS_12) DSP1.E11(VSS_13) DSP1.F3(VSS_14) DSP1.F6(VSS_15) DSP1.F8(VSS_16) DSP1.F10(VSS_17) DSP1.F12(VSS_18) DSP1.F14(VSS_19) DSP1.F16(VSS_20) DSP1.F18(VSS_21) DSP1.G7(VSS_22) DSP1.G9(VSS_23) DSP1.G11(VSS_24) DSP1.G13(VSS_25) DSP1.G15(VSS_26) DSP1.G17(VSS_27) DSP1.H6(VSS_28) DSP1.H8(VSS_29) DSP1.H10(VSS_30) DSP1.H12(VSS_31) DSP1.H14(VSS_32) DSP1.H16(VSS_33) DSP1.H18(VSS_34) DSP1.H20(VSS_35) DSP1.H21(VSS_36) DSP1.H23(VSS_37) DSP1.H25(VSS_38) DSP1.J7(VSS_39) DSP1.J9(VSS_40) DSP1.J11(VSS_41) DSP1.J13(VSS_42) DSP1.J15(VSS_43) DSP1.J17(VSS_44) DSP1.J19(VSS_45) DSP1.J22(VSS_46) DSP1.J23(VSS_47) DSP1.J24(VSS_48) DSP1.K2(VSS_49) DSP1.K6(VSS_50) DSP1.K8(VSS_51) DSP1.K10(VSS_52) DSP1.K12(VSS_53) DSP1.K14(VSS_54) DSP1.K16(VSS_55) DSP1.K18(VSS_56) DSP1.K20(VSS_57) DSP1.K23(VSS_58) DSP1.L7(VSS_59) DSP1.L9(VSS_60) DSP1.L11(VSS_61) DSP1.L13(VSS_62) DSP1.L15(VSS_63) DSP1.L17(VSS_64) DSP1.L19(VSS_65) DSP1.L21(VSS_66) DSP1.L23(VSS_67) DSP1.L25(VSS_68) DSP1.M6(VSS_69) DSP1.M8(VSS_70) DSP1.M10(VSS_71) DSP1.M12(VSS_72) DSP1.M14(VSS_73) DSP1.M16(VSS_74) DSP1.M18(VSS_75) DSP1.M22(VSS_76) DSP1.M23(VSS_77) DSP1.M24(VSS_78) DSP1.N4(VSS_79) DSP1.N7(VSS_80) DSP1.N9(VSS_81) DSP1.N11(VSS_82) DSP1.N13(VSS_83) DSP1.N15(VSS_84) DSP1.N17(VSS_85) DSP1.N19(VSS_86) DSP1.N23(VSS_87) DSP1.P6(VSS_88) DSP1.P8(VSS_89) DSP1.P10(VSS_90) DSP1.P12(VSS_91) DSP1.P14(VSS_92) DSP1.P16(VSS_93) DSP1.P18(VSS_94) DSP1.P20(VSS_95) DSP1.P21(VSS_96) DSP1.P23(VSS_97) DSP1.P25(VSS_98) DSP1.R7(VSS_99) DSP1.R8(VSS_100) DSP1.R9(VSS_101) DSP1.R11(VSS_102) DSP1.R13(VSS_103) DSP1.R15(VSS_104) DSP1.R17(VSS_105) DSP1.R19(VSS_106) DSP1.R22(VSS_107) DSP1.R24(VSS_108) DSP1.T2(VSS_109) DSP1.T6(VSS_110) DSP1.T8(VSS_111) DSP1.T10(VSS_112) DSP1.T12(VSS_113) DSP1.T14(VSS_114) DSP1.T16(VSS_115) DSP1.T18(VSS_116) DSP1.T20(VSS_117) DSP1.U7(VSS_118) DSP1.U9(VSS_119) DSP1.U11(VSS_120) DSP1.U13(VSS_121) DSP1.U15(VSS_122) DSP1.U17(VSS_123) DSP1.U19(VSS_124) DSP1.V6(VSS_125) DSP1.V8(VSS_126) DSP1.V10(VSS_127) DSP1.V12(VSS_128) DSP1.V14(VSS_129) DSP1.V16(VSS_130) DSP1.V18(VSS_131) DSP1.V20(VSS_132) DSP1.W3(VSS_133) DSP1.W7(VSS_134) DSP1.W9(VSS_135) DSP1.W11(VSS_136) DSP1.W13(VSS_137) DSP1.W15(VSS_138) DSP1.W17(VSS_139) DSP1.W19(VSS_140) DSP1.Y6(VSS_141) DSP1.Y8(VSS_142) DSP1.Y10(VSS_143) DSP1.Y12(VSS_144) DSP1.Y14(VSS_145) DSP1.Y16(VSS_146) FAN1.3 R76.1 R87.1 R132.1 R157.1 R158.1 R348.2 R353.1 R364.1 R365.1 R379.2 R380.2 R381.2 R382.1 R383.1 R387.2 R388.1 R389.2 R448.1 R937.2 R1160.2 R1361.2 R1484.2 R1487.2 U5.A9(VSS_1) U5.B1(VSSQ_1) U5.B3(VSS_2) U5.B9(VSSQ_2) U5.D1(VSSQ_3) U5.D8(VSSQ_4) U5.E1(VSS_3) U5.E2(VSSQ_5) U5.E8(VSSQ_6) U5.F9(VSSQ_7) U5.G1(VSSQ_8) U5.G8(VSS_4) U5.G9(VSSQ_9) U5.J2(VSS_5) U5.J8(VSS_6) U5.M1(VSS_7) U5.M9(VSS_8) U5.P1(VSS_9) U5.P9(VSS_10) U5.T1(VSS_11) U5.T9(VSS_12) U6.A9(VSS_1) U6.B1(VSSQ_1) U6.B3(VSS_2) U6.B9(VSSQ_2) U6.D1(VSSQ_3) U6.D8(VSSQ_4) U6.E1(VSS_3) U6.E2(VSSQ_5) U6.E8(VSSQ_6) U6.F9(VSSQ_7) U6.G1(VSSQ_8) U6.G8(VSS_4) U6.G9(VSSQ_9) U6.J2(VSS_5) U6.J8(VSS_6) U6.M1(VSS_7) U6.M9(VSS_8) U6.P1(VSS_9) U6.P9(VSS_10) U6.T1(VSS_11) U6.T9(VSS_12) U13.3(2DIR) U13.8(GND1) U13.9(GND2) U16.A9(VSS_1) U16.B1(VSSQ_1) U16.B3(VSS_2) U16.B9(VSSQ_2) U16.D1(VSSQ_3) U16.D8(VSSQ_4) U16.E1(VSS_3) U16.E2(VSSQ_5) U16.E8(VSSQ_6) U16.F9(VSSQ_7) U16.G1(VSSQ_8) U16.G8(VSS_4) U16.G9(VSSQ_9) U16.J2(VSS_5) U16.J8(VSS_6) U16.M1(VSS_7) U16.M9(VSS_8) U16.P1(VSS_9) U16.P9(VSS_10) U16.T1(VSS_11) U16.T9(VSS_12) U245.1(GND) ; also on sheet 4 5 6 13 14 15 16 19 20 23 26 27 28 29
VCC1V0: B110.3(OUT) B190.3(OUT) C1267.1 C1277.1 C1280.1 C1283.1 C1284.1 C1295.1 C1300.1 C1493.1 DSP1.J8(CVDD1_1) DSP1.J18(CVDD1_2) DSP1.K9(CVDD1_3) DSP1.K17(CVDD1_4) DSP1.T9(CVDD1_5) DSP1.T17(CVDD1_6) DSP1.U8(CVDD1_7) DSP1.U18(CVDD1_8) ; also on sheet 27
VCC1V5: B127.3(OUT) B128.3(OUT) B129.3(OUT) B130.3(OUT) C65.1 C66.1 C67.1 C68.1 C69.1 C70.1 C85.1 C86.1 C87.1 C88.1 C89.1 C90.1 C107.1 C108.1 C109.1 C110.1 C111.1 C112.1 C1193.1 C1208.1 C1209.1 C1210.1 C1211.1 C1212.1 C1214.1 C1216.1 C1217.1 C1218.1 C1219.1 C1220.1 C1221.1 C1222.1 C1223.1 C1224.1 C1227.1 C1556.1 C1557.1 C1558.1 C1560.1 C1705.1 DSP1.B10(DVDD15_1) DSP1.C6(DVDD15_2) DSP1.C17(DVDD15_3) DSP1.C21(DVDD15_4) DSP1.D2(DVDD15_5) DSP1.D4(DVDD15_6) DSP1.D8(DVDD15_7) DSP1.D13(DVDD15_8) DSP1.D15(DVDD15_9) DSP1.D19(DVDD15_10) DSP1.F7(DVDD15_11) DSP1.F9(DVDD15_12) DSP1.F11(DVDD15_13) DSP1.F13(DVDD15_14) DSP1.F17(DVDD15_15) DSP1.F19(DVDD15_16) DSP1.G8(DVDD15_17) DSP1.G10(DVDD15_18) DSP1.G12(DVDD15_19) DSP1.G14(DVDD15_20) DSP1.G16(DVDD15_21) DSP1.G18(DVDD15_22) R390.2 U5.A1(VDDQ_1) U5.A8(VDDQ_2) U5.B2(VDD_1) U5.C1(VDDQ_3) U5.C9(VDDQ_4) U5.D2(VDDQ_5) U5.D9(VDD_2) U5.E9(VDDQ_6) U5.F1(VDDQ_7) U5.G7(VDD_3) U5.H2(VDDQ_8) U5.H9(VDDQ_9) U5.K2(VDD_4) U5.K8(VDD_5) U5.N1(VDD_6) U5.N9(VDD_7) U5.R1(VDD_8) U5.R9(VDD_9) U6.A1(VDDQ_1) U6.A8(VDDQ_2) U6.B2(VDD_1) U6.C1(VDDQ_3) U6.C9(VDDQ_4) U6.D2(VDDQ_5) U6.D9(VDD_2) U6.E9(VDDQ_6) U6.F1(VDDQ_7) U6.G7(VDD_3) U6.H2(VDDQ_8) U6.H9(VDDQ_9) U6.K2(VDD_4) U6.K8(VDD_5) U6.N1(VDD_6) U6.N9(VDD_7) U6.R1(VDD_8) U6.R9(VDD_9) U16.A1(VDDQ_1) U16.A8(VDDQ_2) U16.B2(VDD_1) U16.C1(VDDQ_3) U16.C9(VDDQ_4) U16.D2(VDDQ_5) U16.D9(VDD_2) U16.E9(VDDQ_6) U16.F1(VDDQ_7) U16.G7(VDD_3) U16.H2(VDDQ_8) U16.H9(VDDQ_9) U16.K2(VDD_4) U16.K8(VDD_5) U16.N1(VDD_6) U16.N9(VDD_7) U16.R1(VDD_8) U16.R9(VDD_9) ; also on sheet 5 14 15
VCC1V8: B131.1(IN) B132.1(IN) C355.2 C1176.1 C1177.1 C1178.1 C1179.1 C1180.1 C1181.1 C1182.1 C1183.1 C1184.1 C1185.1 C1186.1 C1187.1 C1188.1 C1189.1 C1190.1 C1191.1 C1192.1 C1194.1 C1195.1 C1196.1 C1197.1 C1198.1 C1199.1 C1200.1 C1201.1 C1213.1 C1700.1 C1702.1 C1703.1 C1704.1 C1706.1 C1707.1 C1708.1 C1709.1 C1710.1 C1711.1 C1712.1 DSP1.A24(DVDD18_1) DSP1.AB23(DVDD18_34) DSP1.AC16(DVDD18_35) DSP1.AC20(DVDD18_36) DSP1.E21(DVDD18_2) DSP1.G3(DVDD18_3) DSP1.G6(DVDD18_4) DSP1.H7(DVDD18_5) DSP1.H19(DVDD18_6) DSP1.H24(DVDD18_7) DSP1.J6(DVDD18_8) DSP1.K3(DVDD18_9) DSP1.K7(DVDD18_10) DSP1.L6(DVDD18_11) DSP1.M7(DVDD18_12) DSP1.N3(DVDD18_13) DSP1.N6(DVDD18_14) DSP1.P7(DVDD18_15) DSP1.R6(DVDD18_16) DSP1.R20(DVDD18_17) DSP1.T3(DVDD18_18) DSP1.T7(DVDD18_19) DSP1.T19(DVDD18_20) DSP1.T24(DVDD18_21) DSP1.U6(DVDD18_22) DSP1.U20(DVDD18_23) DSP1.V7(DVDD18_24) DSP1.V19(DVDD18_25) DSP1.W6(DVDD18_26) DSP1.W14(DVDD18_27) DSP1.W16(DVDD18_28) DSP1.W18(DVDD18_29) DSP1.W20(DVDD18_30) DSP1.Y3(DVDD18_31) DSP1.Y13(DVDD18_32) DSP1.Y17(DVDD18_33) R1958.2 U245.2(VREF1) ; also on sheet 4 5 6 13 15 16 28
VCC1V8_AUX: C1128.2 U13.1(VCCA) U13.2(1DIR) ; also on sheet 6 15 26 29
VCC1V8_AVDD1: B132.3(OUT) C1205.1 C1206.1 C1207.1 DSP1.Y15(AVDDA1)
VCC1V8_AVDD2: B131.3(OUT) C1202.1 C1203.1 C1204.1 DSP1.F20(AVDDA2)
VCC3V3_AUX: C1160.2 R90.2 R175.2 R339.1 R445.1 R446.1 R447.1 R449.1 U13.16(VCCB) ; also on sheet 4 6 13 14 15 16 20 23 26 27 28 29
VCC3V3_MP_AMC: AMC1.4(MP) ; also on sheet 23
VCC12: C526.1 FAN1.2 ; also on sheet 14 27
VCC12_AMC: AMC1.2(PWR_12V_1) AMC1.9(PWR_12V_2) AMC1.18(PWR_12V_3) AMC1.27(PWR_12V_4) AMC1.42(PWR_12V_5) AMC1.57(PWR_12V_6) AMC1.72(PWR_12V_7) AMC1.84(PWR_12V_8) ; also on sheet 14
VDDR1: B127.1(IN) C1477.1 C1478.1 C1479.1 C1480.1 DSP1.M20(VDDR1)
VDDR2: B128.1(IN) C1481.1 C1482.1 C1483.1 C1484.1 DSP1.AA9(VDDR2)
VDDR3: B129.1(IN) C1485.1 C1486.1 C1487.1 C1488.1 DSP1.AA3(VDDR3)
VDDR4: B130.1(IN) C1489.1 C1490.1 C1491.1 C1492.1 DSP1.AA5(VDDR4)
VDDT1: B110.1(IN) C1296.1 C1297.1 C1298.1 C1299.1 DSP1.K19(VDDT1_1) DSP1.L20(VDDT1_2) DSP1.M19(VDDT1_3) DSP1.N20(VDDT1_4)
VDDT2: B190.1(IN) C1287.1 C1288.1 C1289.1 C1291.1 C1292.1 C1294.1 DSP1.W8(VDDT2_1) DSP1.W10(VDDT2_2) DSP1.W12(VDDT2_3) DSP1.Y7(VDDT2_4) DSP1.Y9(VDDT2_5) DSP1.Y11(VDDT2_6)
AMC_JTAG_RST#: AMC1.167(~{TRST}) R448.2 ; also on sheet 6
AMC_JTAG_TCK: AMC1.165(TCK) R449.2 ; also on sheet 6
AMC_JTAG_TDI: AMC1.169(TDI) R445.2 ; also on sheet 6
AMC_JTAG_TDO: AMC1.168(TDO) R446.2 ; also on sheet 6
AMC_JTAG_TMS: AMC1.166(TMS) R447.2 ; also on sheet 6
AMC_P12_McBSP_RX0: AMC1.112(Rx12+) U13.11(2B1)
AMC_P12_McBSP_RX1: AMC1.111(Rx12-) U13.10(2B2)
AMC_P12_McBSP_TX0: AMC1.115(Tx12+) U13.13(1B1)
AMC_P12_McBSP_TX1: AMC1.114(Tx12-) U13.12(1B2)
AMC_SGMII_RXN: AMC1.15(Rx0-) ; also on sheet 19
AMC_SGMII_RXP: AMC1.14(Rx0+) ; also on sheet 19
AMC_SGMII_TXN: AMC1.12(Tx0-) ; also on sheet 19
AMC_SGMII_TXP: AMC1.11(Tx0+) ; also on sheet 19
AMCC_P4_PCIe_RX1N: AMC1.48(Rx4-) ; also on sheet 13
AMCC_P4_PCIe_RX1P: AMC1.47(Rx4+) ; also on sheet 13
AMCC_P4_PCIe_TX1N: C302.1 ; also on sheet 13
AMCC_P4_PCIe_TX1P: C301.1 ; also on sheet 13
AMCC_P5_PCIe_RX2N: AMC1.54(Rx5-) ; also on sheet 13
AMCC_P5_PCIe_RX2P: AMC1.53(Rx5+) ; also on sheet 13
AMCC_P5_PCIe_TX2N: C369.1 ; also on sheet 13
AMCC_P5_PCIe_TX2P: C326.1 ; also on sheet 13
AMCC_P8_SRIO1_RXN: AMC1.87(Rx8-) ; also on sheet 13
AMCC_P8_SRIO1_RXP: AMC1.88(Rx8+) ; also on sheet 13
AMCC_P8_SRIO1_TXN: AMC1.90(Tx8-) ; also on sheet 13
AMCC_P8_SRIO1_TXP: AMC1.91(Tx8+) ; also on sheet 13
AMCC_P9_SRIO2_RXN: AMC1.93(Rx9-) ; also on sheet 13
AMCC_P9_SRIO2_RXP: AMC1.94(Rx9+) ; also on sheet 13
AMCC_P9_SRIO2_TXN: AMC1.96(Tx9-) ; also on sheet 13
AMCC_P9_SRIO2_TXP: AMC1.97(Tx9+) ; also on sheet 13
AMCC_P10_SRIO3_RXN: AMC1.99(Rx10-) ; also on sheet 13
AMCC_P10_SRIO3_RXP: AMC1.100(Rx10+) ; also on sheet 13
AMCC_P10_SRIO3_TXN: AMC1.102(Tx10-) ; also on sheet 13
AMCC_P10_SRIO3_TXP: AMC1.103(Tx10+) ; also on sheet 13
AMCC_P11_SRIO4_RXN: AMC1.105(Rx11-) ; also on sheet 13
AMCC_P11_SRIO4_RXP: AMC1.106(Rx11+) ; also on sheet 13
AMCC_P11_SRIO4_TXN: AMC1.108(Tx11-) ; also on sheet 13
AMCC_P11_SRIO4_TXP: AMC1.109(Tx11+) ; also on sheet 13
CVDD: C1228.1 C1229.1 C1230.1 C1231.1 C1232.1 C1233.1 C1234.1 C1235.1 C1236.1 C1237.1 C1238.1 C1239.1 C1240.1 C1241.1 C1248.1 C1249.1 C1250.1 C1251.1 C1252.1 C1253.1 C1254.1 C1255.1 C1256.1 C1257.1 C1258.1 C1259.1 C1260.1 C1261.1 C1262.1 C1263.1 C1266.1 C1269.1 C1270.1 C1271.1 C1272.1 C1273.1 C1274.1 C1278.1 C1279.1 C1281.1 C1282.1 C1286.1 C1290.1 C1568.1 C1570.1 C1571.1 DSP1.H9(CVDD_1) DSP1.H11(CVDD_2) DSP1.H13(CVDD_3) DSP1.H15(CVDD_4) DSP1.H17(CVDD_5) DSP1.J10(CVDD_6) DSP1.J12(CVDD_7) DSP1.J14(CVDD_8) DSP1.J16(CVDD_9) DSP1.K11(CVDD_10) DSP1.K13(CVDD_11) DSP1.K15(CVDD_12) DSP1.L8(CVDD_13) DSP1.L10(CVDD_14) DSP1.L12(CVDD_15) DSP1.L14(CVDD_16) DSP1.L16(CVDD_17) DSP1.L18(CVDD_18) DSP1.M9(CVDD_19) DSP1.M11(CVDD_20) DSP1.M13(CVDD_21) DSP1.M15(CVDD_22) DSP1.M17(CVDD_23) DSP1.N8(CVDD_24) DSP1.N10(CVDD_25) DSP1.N12(CVDD_26) DSP1.N14(CVDD_27) DSP1.N16(CVDD_28) DSP1.N18(CVDD_29) DSP1.P9(CVDD_30) DSP1.P11(CVDD_31) DSP1.P13(CVDD_32) DSP1.P15(CVDD_33) DSP1.P17(CVDD_34) DSP1.P19(CVDD_35) DSP1.R10(CVDD_36) DSP1.R12(CVDD_37) DSP1.R14(CVDD_38) DSP1.R16(CVDD_39) DSP1.R18(CVDD_40) DSP1.T11(CVDD_41) DSP1.T13(CVDD_42) DSP1.T15(CVDD_43) DSP1.U10(CVDD_44) DSP1.U12(CVDD_45) DSP1.U14(CVDD_46) DSP1.U16(CVDD_47) DSP1.V9(CVDD_48) DSP1.V11(CVDD_49) DSP1.V13(CVDD_50) DSP1.V15(CVDD_51) DSP1.V17(CVDD_52) ; also on sheet 27
DSP0_DDR3_EA0: U5.N3(A0) U6.N3(A0) U16.N3(A0) ; also on sheet 5
DSP0_DDR3_EA1: U5.P7(A1) U6.P7(A1) U16.P7(A1) ; also on sheet 5
DSP0_DDR3_EA2: U5.P3(A2) U6.P3(A2) U16.P3(A2) ; also on sheet 5
DSP0_DDR3_EA3: U5.N2(A3) U6.N2(A3) U16.N2(A3) ; also on sheet 5
DSP0_DDR3_EA4: U5.P8(A4) U6.P8(A4) U16.P8(A4) ; also on sheet 5
DSP0_DDR3_EA5: U5.P2(A5) U6.P2(A5) U16.P2(A5) ; also on sheet 5
DSP0_DDR3_EA6: U5.R8(A6) U6.R8(A6) U16.R8(A6) ; also on sheet 5
DSP0_DDR3_EA7: U5.R2(A7) U6.R2(A7) U16.R2(A7) ; also on sheet 5
DSP0_DDR3_EA8: U5.T8(A8) U6.T8(A8) U16.T8(A8) ; also on sheet 5
DSP0_DDR3_EA9: U5.R3(A9) U6.R3(A9) U16.R3(A9) ; also on sheet 5
DSP0_DDR3_EA10: U5.L7(A10/AP) U6.L7(A10/AP) U16.L7(A10/AP) ; also on sheet 5
DSP0_DDR3_EA11: U5.R7(A11) U6.R7(A11) U16.R7(A11) ; also on sheet 5
DSP0_DDR3_EA12: U5.N7(A12/~{BC}) U6.N7(A12/~{BC}) U16.N7(A12/~{BC}) ; also on sheet 5
DSP0_DDR3_EA13: U5.T3(A13) U6.T3(A13) U16.T3(A13) ; also on sheet 5
DSP0_DDR3_EA14: U5.T7(NC_7) U6.T7(NC_7) U16.T7(NC_7) ; also on sheet 5
DSP0_DDR3_EA15: U5.M7(NC_5) U6.M7(NC_5) U16.M7(NC_5) ; also on sheet 5
DSP0_DDR3_EBA_0: U5.M2(BA0) U6.M2(BA0) U16.M2(BA0) ; also on sheet 5
DSP0_DDR3_EBA_1: U5.N8(BA1) U6.N8(BA1) U16.N8(BA1) ; also on sheet 5
DSP0_DDR3_EBA_2: U5.M3(BA2) U6.M3(BA2) U16.M3(BA2) ; also on sheet 5
DSP0_DDR3_ECAS#: U5.K3(~{CAS}) U6.K3(~{CAS}) U16.K3(~{CAS}) ; also on sheet 5
DSP0_DDR3_ECC0: U6.E3(DQL0) ; also on sheet 5
DSP0_DDR3_ECC1: U6.F7(DQL1) ; also on sheet 5
DSP0_DDR3_ECC2: U6.F2(DQL2) ; also on sheet 5
DSP0_DDR3_ECC3: U6.F8(DQL3) ; also on sheet 5
DSP0_DDR3_ECKE_0: U5.K9(CKE) U6.K9(CKE) U16.K9(CKE) ; also on sheet 5
DSP0_DDR3_ECKN_0: U5.K7(~{CK}) U6.K7(~{CK}) U16.K7(~{CK}) ; also on sheet 5
DSP0_DDR3_ECKP_0: U5.J7(CK) U6.J7(CK) U16.J7(CK) ; also on sheet 5
DSP0_DDR3_ECS_0#: U5.L2(~{CS}) U6.L2(~{CS}) U16.L2(~{CS}) ; also on sheet 5
DSP0_DDR3_EDM_0: U5.E7(DML) ; also on sheet 5
DSP0_DDR3_EDM_1: U5.D3(DMU) ; also on sheet 5
DSP0_DDR3_EDM_2: U16.E7(DML) ; also on sheet 5
DSP0_DDR3_EDM_3: U16.D3(DMU) ; also on sheet 5
DSP0_DDR3_EDM_4: U6.E7(DML) ; also on sheet 5
DSP0_DDR3_EDQ0: U5.E3(DQL0) ; also on sheet 5
DSP0_DDR3_EDQ1: U5.F7(DQL1) ; also on sheet 5
DSP0_DDR3_EDQ2: U5.F2(DQL2) ; also on sheet 5
DSP0_DDR3_EDQ3: U5.F8(DQL3) ; also on sheet 5
DSP0_DDR3_EDQ4: U5.H3(DQL4) ; also on sheet 5
DSP0_DDR3_EDQ5: U5.H8(DQL5) ; also on sheet 5
DSP0_DDR3_EDQ6: U5.G2(DQL6) ; also on sheet 5
DSP0_DDR3_EDQ7: U5.H7(DQL7) ; also on sheet 5
DSP0_DDR3_EDQ8: U5.D7(DQU0) ; also on sheet 5
DSP0_DDR3_EDQ9: U5.C3(DQU1) ; also on sheet 5
DSP0_DDR3_EDQ10: U5.C8(DQU2) ; also on sheet 5
DSP0_DDR3_EDQ11: U5.C2(DQU3) ; also on sheet 5
DSP0_DDR3_EDQ12: U5.A7(DQU4) ; also on sheet 5
DSP0_DDR3_EDQ13: U5.A2(DQU5) ; also on sheet 5
DSP0_DDR3_EDQ14: U5.B8(DQU6) ; also on sheet 5
DSP0_DDR3_EDQ15: U5.A3(DQU7) ; also on sheet 5
DSP0_DDR3_EDQ16: U16.E3(DQL0) ; also on sheet 5
DSP0_DDR3_EDQ17: U16.F7(DQL1) ; also on sheet 5
DSP0_DDR3_EDQ18: U16.F2(DQL2) ; also on sheet 5
DSP0_DDR3_EDQ19: U16.F8(DQL3) ; also on sheet 5
DSP0_DDR3_EDQ20: U16.H3(DQL4) ; also on sheet 5
DSP0_DDR3_EDQ21: U16.H8(DQL5) ; also on sheet 5
DSP0_DDR3_EDQ22: U16.G2(DQL6) ; also on sheet 5
DSP0_DDR3_EDQ23: U16.H7(DQL7) ; also on sheet 5
DSP0_DDR3_EDQ24: U16.D7(DQU0) ; also on sheet 5
DSP0_DDR3_EDQ25: U16.C3(DQU1) ; also on sheet 5
DSP0_DDR3_EDQ26: U16.C8(DQU2) ; also on sheet 5
DSP0_DDR3_EDQ27: U16.C2(DQU3) ; also on sheet 5
DSP0_DDR3_EDQ28: U16.A7(DQU4) ; also on sheet 5
DSP0_DDR3_EDQ29: U16.A2(DQU5) ; also on sheet 5
DSP0_DDR3_EDQ30: U16.B8(DQU6) ; also on sheet 5
DSP0_DDR3_EDQ31: U16.A3(DQU7) ; also on sheet 5
DSP0_DDR3_EDQSN_0: U5.G3(~{DQSL}) ; also on sheet 5
DSP0_DDR3_EDQSN_1: U5.B7(~{DQSU}) ; also on sheet 5
DSP0_DDR3_EDQSN_2: U16.G3(~{DQSL}) ; also on sheet 5
DSP0_DDR3_EDQSN_3: U16.B7(~{DQSU}) ; also on sheet 5
DSP0_DDR3_EDQSN_4: U6.G3(~{DQSL}) ; also on sheet 5
DSP0_DDR3_EDQSP_0: U5.F3(DQSL) ; also on sheet 5
DSP0_DDR3_EDQSP_1: U5.C7(DQSU) ; also on sheet 5
DSP0_DDR3_EDQSP_2: U16.F3(DQSL) ; also on sheet 5
DSP0_DDR3_EDQSP_3: U16.C7(DQSU) ; also on sheet 5
DSP0_DDR3_EDQSP_4: U6.F3(DQSL) ; also on sheet 5
DSP0_DDR3_EMRESETN: U5.T2(~{RESET}) U6.T2(~{RESET}) U16.T2(~{RESET}) ; also on sheet 5
DSP0_DDR3_EODT_0: U5.K1(ODT) U6.K1(ODT) U16.K1(ODT) ; also on sheet 5
DSP0_DDR3_ERAS#: U5.J3(~{RAS}) U6.J3(~{RAS}) U16.J3(~{RAS}) ; also on sheet 5
DSP0_DDR3_EWE#: U5.L3(~{WE}) U6.L3(~{WE}) U16.L3(~{WE}) ; also on sheet 5
DSP_McBSP0_RX: U13.6(2A1) ; also on sheet 13 23
DSP_McBSP0_TX: U13.4(1A1) ; also on sheet 13 23
DSP_McBSP1_RX: U13.7(2A2) ; also on sheet 13 23
DSP_McBSP1_TX: U13.5(1A2) ; also on sheet 13 23
DSP_SCL: U245.3(SCL1) ; also on sheet 4 23
DSP_SCL_AMC: R161.2 R175.1 R484.2 U245.6(SCL2)
DSP_SDA: U245.4(SDA1) ; also on sheet 4 23
DSP_SDA_AMC: R90.1 R160.2 R487.2 U245.5(SDA2)
DSP_VREFSSTL: C113.1 C163.1 C328.1 U5.H1(VREFDQ) U5.M8(VREFCA) U6.H1(VREFDQ) U6.M8(VREFCA) U16.H1(VREFDQ) U16.M8(VREFCA) ; also on sheet 5 15
McBSP_AMC_EN#: R1958.1 U13.14(2~{OE}) U13.15(1~{OE}) ; also on sheet 29
MMC_ENABLE_N: AMC1.41(~{ENABLE}) ; also on sheet 23
MMC_GA0: AMC1.5(GA0) ; also on sheet 23
MMC_GA1: AMC1.17(GA1) ; also on sheet 23
MMC_GA2: AMC1.26(GA2) ; also on sheet 23
MMC_PS_N0: AMC1.83(~{PS0}) D3.2(CATHODE)
MMC_PS_N1: AMC1.3(~{PS1}) D3.1(ANODE)
PCIE_REF_CLK_N: AMC1.81(FCLKA-) ; also on sheet 28
PCIE_REF_CLK_P: AMC1.80(FCLKA+) ; also on sheet 28
SMB_SCL_IPMBL: AMC1.56(SCL_L) ; also on sheet 23
SMB_SDA_IPMBL: AMC1.71(SDA_L) ; also on sheet 23
TCLKA_N: AMC1.75(TCLKA-) ; also on sheet 29
TCLKA_P: AMC1.74(TCLKA+) ; also on sheet 29
TCLKB_N: AMC1.78(TCLKB-) ; also on sheet 20
TCLKB_P: AMC1.77(TCLKB+) ; also on sheet 20
TCLKC_N: AMC1.135(TCLKC-) ; also on sheet 29
TCLKC_P: AMC1.136(TCLKC+) ; also on sheet 29
TCLKD_N: AMC1.138(TCLKD-) ; also on sheet 29
TCLKD_P: AMC1.139(TCLKD+) ; also on sheet 29
TRIP1: ESD1.1 ESD1.4 R157.2 R158.2 R936.1
TRIP2: ESD1.2 R937.1
TRIP3: ESD1.3 R936.2
N34799622: R76.2 U5.L8(ZQ)
N34813638: R132.2 U16.L8(ZQ)
N44717316: DSP1.G19(RSV0A) R364.2
N44717330: DSP1.G20(RSV0B) R365.2
N60746967: AMC1.129(Rx15-) R161.1
N60747544: AMC1.50(Tx5+) C326.2
N60747547: AMC1.51(Tx5-) C369.2
N60747553: AMC1.44(Tx4+) C301.2
N60747556: AMC1.45(Tx4-) C302.2
N60748157: AMC1.130(Rx15+) R160.1
N69781656: R348.1 U6.D7(DQU0)
N69783733: R353.2 U6.C3(DQU1)
N69786452: R379.1 U6.C8(DQU2)
N69786454: R382.2 U6.C2(DQU3)
N69789179: R380.1 U6.A7(DQU4)
N69789181: R381.1 U6.A2(DQU5)
N69789183: R383.2 U6.A3(DQU7)
N69789185: R388.2 U6.B8(DQU6)
N69791128: R390.1 U6.C7(DQSU)
N69793219: R389.1 U6.B7(~{DQSU})
N69805002: R387.1 U6.D3(DMU)
N69814752: R87.2 U6.L8(ZQ)
N69827160: R1160.1 U6.H3(DQL4)
N69827162: R1361.1 U6.H8(DQL5)
N69827164: R1487.1 U6.H7(DQL7)
N69827166: R1484.1 U6.G2(DQL6)
N70154042: C411.1 R339.2 U245.7(VREF2) U245.8(EN)
N73023274: AMC1.159(Rx20-) R487.1
N73023292: AMC1.160(Rx20+) R484.1

Not connected (* = marked no-connect by the designer): AMC1 6(RSRVD6)* 8(RSRVD8)* 20(Tx1+)* 21(Tx1-)* 23(Rx1+)* 24(Rx1-)* 29(Tx2+)* 30(Tx2-)* 32(Rx2+)* 33(Rx2-)* 35(Tx3+)* 36(Tx3-)* 38(Rx3+)* 39(Rx3-)* 59(Tx6+)* 60(Tx6-)* 62(Rx6+)* 63(Rx6-)* 65(Tx7+)* 66(Tx7-)* 68(Rx7+)* 69(Rx7-)* 117(Rx13-) 118(Rx13+) 120(Tx13-) 121(Tx13+) 123(Rx14-)* 124(Rx14+)* 126(Tx14-)* 127(Tx14+)* 132(Tx15-)* 133(Tx15+)* 141(Rx17-)* 142(Rx17+)* 144(Tx17-)* 145(Tx17+)* 147(Rx18-)* 148(Rx18+)* 150(Tx18-)* 151(Tx18+)* 153(Rx19-)* 154(Rx19+)* 156(Tx19-)* 157(Tx19+)* 162(Tx20-)* 163(Tx20+)*; FAN1 1*; U5 J1(NC_1)* J9(NC_2)* L1(NC_3)* L9(NC_4)*; U6 J1(NC_1)* J9(NC_2)* L1(NC_3)* L9(NC_4)*; U16 J1(NC_1)* J9(NC_2)* L1(NC_3)* L9(NC_4)*

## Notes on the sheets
sheet 7
- 1.0V
- 1.0V & 1.5V for SERDES
- Place near to DSP
- GROUND
sheet 8
- DDR3 MEMORY INTERFACE
- 20 mil trace width
- 20 mil trace width
- Supported Memories (96 FBGA) :
- Mfgr
- 512MB (256MB x 2)
- 1024MB (512MB x 2)
- Micron
- MT41J128M16HA-125
- MT41J256M16RE-125
- DDR3 ECC INTERFACE
- - Data bits can be swapped within the byte
  lane to ease routing.
  - Address/Command/Control/Clock routing
  must be Fly-By in byte order ECC, 0, 1, 2, 3.
- 20 mil trace width
- Supported ECC Chip (96 FBGA) :
- Mfgr
- 256MB
- 512MB
- Micron
- MT41J128M16HA-125
- MT41J256M16RE-125
sheet 9
- 1.8V
- Place near to DSP
- 1.5V
- Place near to DSP
- 0.9V - 1.1V (SMART REFLEX)
- Place near to DSP
sheet 10
- MANAGEMENT MAP
sheet 11
- CLOCK DIAGRAM
sheet 12
- AMC CONNECTOR
- FAN CONNECTOR
- Front Panel and ESD Strip
- Management Power
- OE# = 0
  DIR = 0 --> B to A
  DIR = 1 --> A to B
